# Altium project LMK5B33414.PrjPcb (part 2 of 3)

## Sheet LMK5B33414_Logic.SchDoc
size C; Date: Not shown in title block; ApprovedBy: Not shown in title block; CheckedBy: Not shown in title block; Author: Not shown in title block; CompanyName: Not shown in title block; Engineer: Not shown in title block; Organization: Not shown in title block; Address1: Not shown in title block; Address2: Not shown in title block; Address3: Not shown in title block; Address4: Not shown in title block; DocumentNumber: 2; Revision: Use project parameter SCH_Rev; SheetNumber: 2; SheetTotal: 3; PageSetup: Record=PageOptions¦CenterHorizontal=True¦CenterVertical=True¦PrintScale=1.00¦XCorrection=1.00¦YCorrection=1.00¦PrintKind=0¦BorderSize=5000000¦LeftOffset=0¦BottomOffset=0¦Orientation=2¦PaperLength=1000¦PaperWidth=1000¦Scale=100¦PaperSource=15¦PrintQuality=600¦MediaType=1¦DitherType=10¦PaperKind=Letter¦PrintScaleMode=1
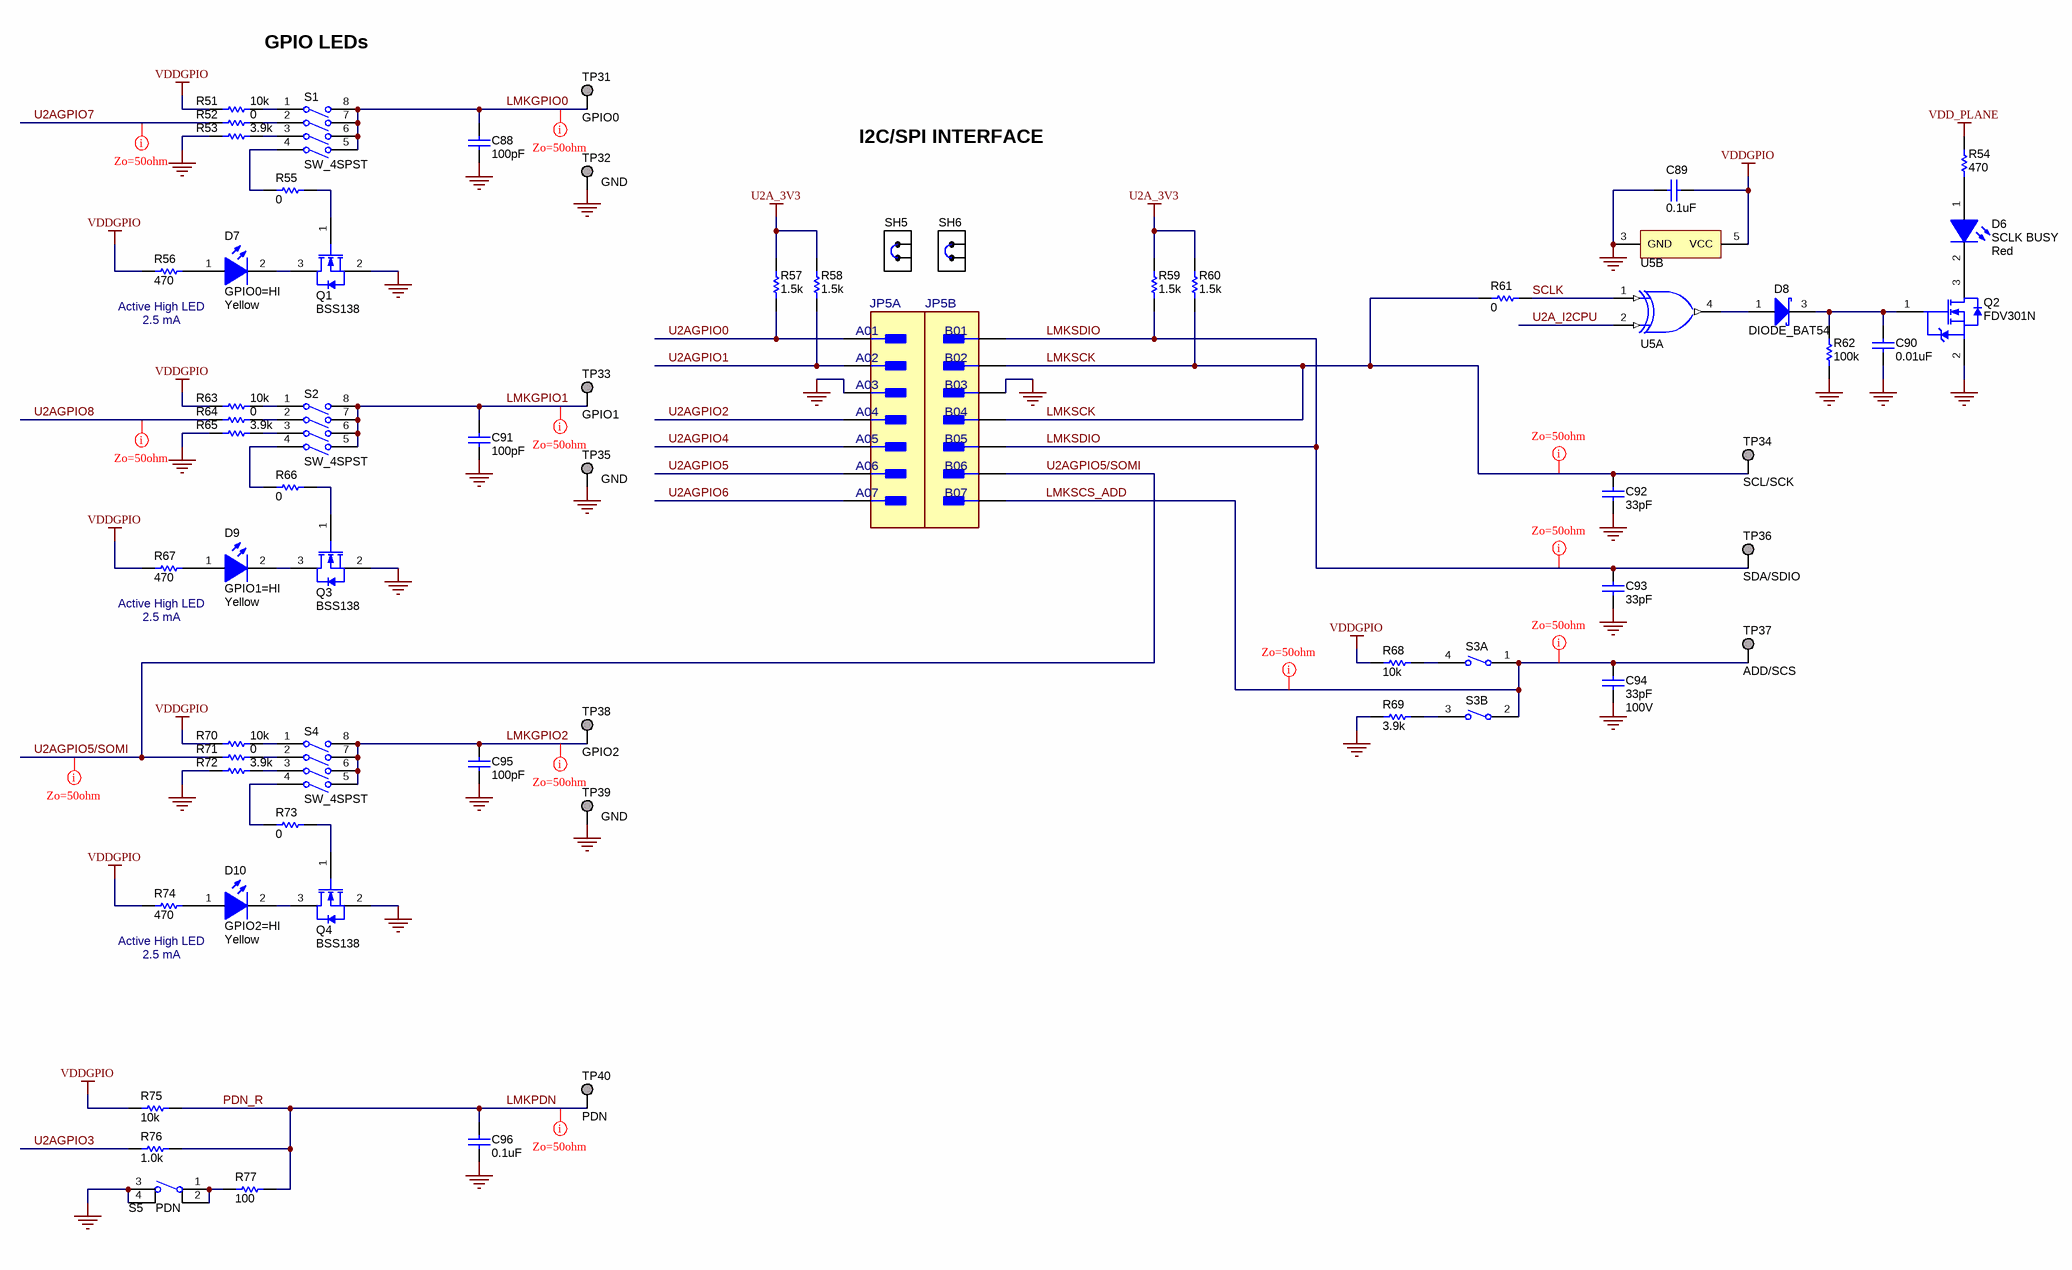
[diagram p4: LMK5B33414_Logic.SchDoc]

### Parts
C88  ValueDisplayed: 100pF  [0603]  (hidden comment: Capacitor)
C89  ValueDisplayed: 0.1uF  [0603]  (hidden comment: Capacitor)
C90  ValueDisplayed: 0.01uF  [0603]  (hidden comment: Capacitor)
C91  ValueDisplayed: 100pF  [0603]  (hidden comment: Capacitor)
C92  ValueDisplayed: 33pF  [0603]  (hidden comment: Capacitor)
C93  ValueDisplayed: 33pF  [0603]  (hidden comment: Capacitor)
C94  ValueDisplayed: 33pF  VDC_V: 100V  [0603]  (hidden comment: 06031A330JAT2A)
C95  ValueDisplayed: 100pF  [0603]  (hidden comment: Capacitor)
C96  ValueDisplayed: 0.1uF  [0603]  (hidden comment: C0603C104J3RACTU)
D6  SCLK BUSY  value Red  [LED_LTST-C170_Red]
D7  GPIO0=HI  value Yellow  [LED_LTST-C170]
D8  DIODE_BAT54  [SOT-23]
D9  GPIO1=HI  value Yellow  [LED_LTST-C170]
D10  GPIO2=HI  value Yellow  [LED_LTST-C170]
JP5  54202-G0807LF  [FP-54202-G0807LF_HDR14-MFG]  (value not drawn)  (parts A,B of 2)
Q1  BSS138  [SOT-23]
Q2  FDV301N  [SOT-23]
Q3  BSS138  [SOT-23]
Q4  BSS138  [SOT-23]
R51  ValueDisplayed: 10k  [0603]  (hidden comment: Resistor)
R52  ValueDisplayed: 0  [0603]  (hidden comment: Resistor)
R53  ValueDisplayed: 3.9k  [0603]  (hidden comment: CRCW06033K90JNEA)
R54  ValueDisplayed: 470  [0603]  (hidden comment: Resistor)
R55  ValueDisplayed: 0  [0603L]  (hidden comment: Resistor)
R56  ValueDisplayed: 470  [0603]  (hidden comment: Resistor)
R57  ValueDisplayed: 1.5k  [0603]  (hidden comment: Resistor)
R58  ValueDisplayed: 1.5k  [0603]  (hidden comment: Resistor)
R59  ValueDisplayed: 1.5k  [0603]  (hidden comment: Resistor)
R60  ValueDisplayed: 1.5k  [0603]  (hidden comment: Resistor)
R61  ValueDisplayed: 0  [0603]  (hidden comment: Resistor)
R62  ValueDisplayed: 100k  [0603]  (hidden comment: Resistor)
R63  ValueDisplayed: 10k  [0603]  (hidden comment: Resistor)
R64  ValueDisplayed: 0  [0603]  (hidden comment: Resistor)
R65  ValueDisplayed: 3.9k  [0603]  (hidden comment: CRCW06033K90JNEA)
R66  ValueDisplayed: 0  [0603L]  (hidden comment: Resistor)
R67  ValueDisplayed: 470  [0603]  (hidden comment: Resistor)
R68  ValueDisplayed: 10k  [0603]  (hidden comment: Resistor)
R69  ValueDisplayed: 3.9k  [0603]  (hidden comment: Resistor)
R70  ValueDisplayed: 10k  [0603]  (hidden comment: Resistor)
R71  ValueDisplayed: 0  [0603]  (hidden comment: Resistor)
R72  ValueDisplayed: 3.9k  [0603]  (hidden comment: CRCW06033K90JNEA)
R73  ValueDisplayed: 0  [0603L]  (hidden comment: Resistor)
R74  ValueDisplayed: 470  [0603]  (hidden comment: Resistor)
R75  ValueDisplayed: 10k  [0603]  (hidden comment: Resistor)
R76  ValueDisplayed: 1.0k  [0603]  (hidden comment: Resistor)
R77  ValueDisplayed: 100  [0603]  (hidden comment: ESR03EZPJ101)
S1  SW_4SPST  [SW_219-4LPST]
S2  SW_4SPST  [SW_219-4LPST]
S3  SW_219-2LPST  [SW_219-2LPST]  (value not drawn)  (parts A,B of 2)
S4  SW_4SPST  [SW_219-4LPST]
S5  PDN  [SW_FSM4JSMA]
SH5  SNT-100-BK-G  [SNT-100-BK-G]  (value not drawn)
SH6  SNT-100-BK-G  [SNT-100-BK-G]  (value not drawn)
TP31  GPIO0  [Keystone_5019]
TP32  GND  [Keystone_5019]
TP33  GPIO1  [Keystone_5019]
TP34  SCL/SCK  [Keystone_5019]
TP35  GND  [Keystone_5019]
TP36  SDA/SDIO  [Keystone_5019]
TP37  ADD/SCS  [Keystone_5019]
TP38  GPIO2  [Keystone_5019]
TP39  GND  [Keystone_5019]
TP40  PDN  [Keystone_5019]
U5  TI-XOR-1-2IN-5  [DBV0005A_N]  (value not drawn)  (parts A,B of 2)

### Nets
GND: C88.2 C89.1 C90.2 C91.2 C92.2 C93.2 C94.2 C95.2 C96.2 JP5.A03 JP5.B03 Q1.2(S) Q2.2(S) Q3.2(S) Q4.2(S) R53.1 R62.1 R65.1 R69.1 R72.1 S5.3 S5.4 TP32.1 TP35.1 TP39.1 U5.3(GND)
U2A_3V3: R57.2 R58.2 R59.2 R60.2
VDD_PLANE: R54.2
VDDGPIO: C89.2 R51.1 R56.2 R63.1 R67.2 R68.1 R70.1 R74.2 R75.1 U5.5(VCC)
LMKGPIO0: C88.1 S1.5(B4) S1.6(B3) S1.7(B2) S1.8(B1) TP31.1
LMKGPIO1: C91.1 S2.5(B4) S2.6(B3) S2.7(B2) S2.8(B1) TP33.1
LMKGPIO2: C95.1 S4.5(B4) S4.6(B3) S4.7(B2) S4.8(B1) TP38.1
LMKPDN: C96.1 R75.2 R76.2 R77.1 TP40.1  [also labelled PDN_R]
LMKSCK: C92.1 JP5.B02 JP5.B04 R60.1 R61.1 TP34.1
LMKSCS_ADD: C94.1 JP5.B07 S3.1(1A) S3.2(2A) TP37.1
LMKSDIO: C93.1 JP5.B01 JP5.B05 R59.1 TP36.1
SCLK: R61.2 U5.1(A)
U2A_I2CPU: U5.2(B)
U2AGPIO0: JP5.A01 R57.1
U2AGPIO1: JP5.A02 R58.1
U2AGPIO2: JP5.A04
U2AGPIO3: R76.1
U2AGPIO4: JP5.A05
U2AGPIO5: JP5.A06
U2AGPIO5/SOMI: JP5.B06 R71.2
U2AGPIO6: JP5.A07
U2AGPIO7: R52.1
U2AGPIO8: R64.1
NetC90_1: C90.1 D8.3(K) Q2.1(G) R62.2
NetD6_1: D6.1(A) R54.1
NetD6_2: D6.2(K) Q2.3(D)
NetD7_1: D7.1(A) R56.1
NetD7_2: D7.2(K) Q1.3(D)
NetD8_1: D8.1(A) U5.4(Y)
NetD9_1: D9.1(A) R67.1
NetD9_2: D9.2(K) Q3.3(D)
NetD10_1: D10.1(A) R74.1
NetD10_2: D10.2(K) Q4.3(D)
NetQ1_1: Q1.1(G) R55.2
NetQ3_1: Q3.1(G) R66.2
NetQ4_1: Q4.1(G) R73.2
NetR51_2: R51.2 S1.1(A1)
NetR52_2: R52.2 S1.2(A2)
NetR53_2: R53.2 S1.3(A3)
NetR55_1: R55.1 S1.4(A4)
NetR63_2: R63.2 S2.1(A1)
NetR64_2: R64.2 S2.2(A2)
NetR65_2: R65.2 S2.3(A3)
NetR66_1: R66.1 S2.4(A4)
NetR68_2: R68.2 S3.4(1B)
NetR69_2: R69.2 S3.3(2B)
NetR70_2: R70.2 S4.1(A1)
NetR71_1: R71.1 S4.2(A2)
NetR72_2: R72.2 S4.3(A3)
NetR73_1: R73.1 S4.4(A4)
NetR77_2: R77.2 S5.1 S5.2

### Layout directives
rule Impedance Constraint [Min = 45.00    Max = 55.00    ]: LMKGPIO0, LMKGPIO1, LMKGPIO2, LMKPDN, LMKSCK, LMKSCS_ADD, LMKSDIO, U2AGPIO5/SOMI, U2AGPIO7, U2AGPIO8

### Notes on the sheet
- GPIO LEDs
- I2C/SPI INTERFACE
- Active High LED
  2.5 mA

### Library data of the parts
C88 C91 C95 = CMP-0006763-4: CAP, CERM, 100 pF, 50 V, +/- 5%, C0G/NP0, 0603; PartNumber: 06035A101JAT2A; Manufacturer: AVX; Polarized: N; Value: 100pF; U/M: EA; ESR_ohm: 1.19d; Value1: 0.119 ohm; VDC_V: 50V; TaMin_C: -55°C; TaMax_C: 125°C; AEC Category: Q200; SizeArea_mm2: 1.28; SizeAreaWB_mm2: 4.68; SizeX_mm: 1.6; SizeY_mm: 0.8; SizeZ_mm: 1
C89 = CMP-0006857-4: CAP, CERM, 0.1 uF, 16 V, +/- 5%, X7R, 0603; PartNumber: C0603C104J4RACTU; Manufacturer: Kemet; Polarized: N; Value: 0.1uF; U/M: EA; Cap_F: 100nF; Value1: Unknown; VDC_V: 16V; TaMin_C: -55°C; TaMax_C: 125°C; AEC Category: Q200; SizeArea_mm2: 1.28; SizeAreaWB_mm2: 4.68; SizeX_mm: 1.6; SizeY_mm: 0.8; SizeZ_mm: 1
C90 = CMP-0006850-4: CAP, CERM, 0.01 uF, 50 V, +/- 5%, X7R, 0603; PartNumber: C0603C103J5RACTU; Manufacturer: Kemet; Polarized: N; Value: 0.01uF; U/M: EA; Cap_F: 10nF; Value1: Unknown; VDC_V: 50V; TaMin_C: -55°C; TaMax_C: 125°C; SizeArea_mm2: 1.28; SizeAreaWB_mm2: 4.68; SizeX_mm: 1.6; SizeY_mm: 0.8; SizeZ_mm: 1; AEC Category: Q200
C92 C93 = CMP-0006722-4: CAP, CERM, 33 pF, 100 V, +/- 5%, C0G/NP0, 0603; PartNumber: 06031A330JAT2A; Manufacturer: AVX; Polarized: N; Value: 33pF; U/M: EA; ESR_ohm: 2.09d; Value1: 0.209 ohm; VDC_V: 100V; TaMin_C: -55°C; TaMax_C: 125°C; AEC Category: Q200; SizeArea_mm2: 1.28; SizeAreaWB_mm2: 4.68; SizeX_mm: 1.6; SizeY_mm: 0.8; SizeZ_mm: 1
C94 = CMP-0006722-4: CAP, CERM, 33 pF, 100 V, +/- 5%, C0G/NP0, 0603; Manufacturer: AVX; Polarized: N; Value: 33pF; U/M: EA; ESR_ohm: 2.09d; Value1: 0.209 ohm; TaMin_C: -55°C; TaMax_C: 125°C; AEC Category: Q200; SizeArea_mm2: 1.28; SizeAreaWB_mm2: 4.68; SizeX_mm: 1.6; SizeY_mm: 0.8; SizeZ_mm: 1
C96 = CMP-0006856-6: CAP, CERM, 0.1 uF, 25 V, +/- 5%, X7R, 0603; Manufacturer: Kemet; Polarized: N; Value: 0.1uF; U/M: EA; Cap_F: 100nF; Value1: Unknown; VDC_V: 25V; TaMin_C: -55°C; TaMax_C: 125°C; AEC Category: Q200; SizeArea_mm2: 1.28; SizeAreaWB_mm2: 4.68; SizeX_mm: 1.6; SizeY_mm: 0.8; SizeZ_mm: 1
D6 = CMP-0002829-2: LED, Red, SMD; Manufacturer: Lite-On; PartNumber: LTST-C170KRKT; Type: AlInGaP; Vf_V: 2V; Io_A: 20mA; Value1: W; U/M: EA; SizeAreaWB_mm2: 6.75; SizeArea_mm2: 2.5; SizeX_mm: 2; SizeY_mm: 1.25; SizeZ_mm: 1.2
D7 D9 D10 = CMP-0002862-2: LED, Yellow , SMD; Manufacturer: Lite-On; PartNumber: LTST-C170KSKT; Type: AlInGaP; Vf_V: 2V; Io_A: 20mA; Value1: W; SizeArea_mm2: 2.5; SizeAreaWB_mm2: 6.75; SizeX_mm: 2; SizeY_mm: 1.25; SizeZ_mm: 1.2
D8 = CMP-0028451-2: Diode, Schottky, 30 V, 0.2 A, SOT-23; PartNumber: BAT54-7-F; Manufacturer: Diodes Inc.; Vf_V: 6.5dV; Value: 30V; Value1: 0.2A; Value2: 0.65V; Io_A: 2dA; TJmax_C: 125°C; SizeAreaWB_mm2: 14; SizeArea_mm2: 7.5; SizeX_mm: 2.5; SizeY_mm: 3; SizeZ_mm: 1.1; AEC Category: Q101; Green_Lifecycle: Active; Green_REACh: Passed
JP5 = CMP-0088459-1: Connector Header Surface Mount 14 position 0.100" (2.54mm); Manufacturer: Amphenol ICC; Standoff Height: 1.01mm; Voltage_V: 1.5kV; Conn Gender: Male; ContactFinish: Gold,Nickel; AEC Qualified: No; SizeZ_mm: 9.98mm; Conn Orientation: Straight; Current_A: 3A; Row_Count: 2
Q1 Q3 Q4 = CMP-0000755-1: MOSFET, N-CH, 50 V, 0.22 A, SOT-23; Manufacturer: Fairchild Semiconductor; Alternate Manufacturer: None; U/M: EA; ChType: N; Value: 50V; Rdson45_ohm: 6; Value2: 1.7 nC; QgTyp_nC: 1.7; Vgs_V: 20V; IdsMax_A: 2.2dA; AEC Category: Q101; SizeArea_mm2: 7.5; SizeAreaWB_mm2: 14; SizeX_mm: 2.5; SizeY_mm: 3; SizeZ_mm: 1.1
Q2 = CMP-0000281-1: MOSFET, N-CH, 25 V, 0.22 A, SOT-23; Manufacturer: Fairchild Semiconductor; Alternate Manufacturer: None; U/M: EA; ChType: N; Value: 25V; Rdson45_ohm: 4; Value2: 0.49 nC; QgTyp_nC: 0.49; Vgs_V: 8V; IdsMax_A: 2.2dA; SizeAreaWB_mm2: 14; SizeArea_mm2: 7.5; SizeX_mm: 2.5; SizeY_mm: 3; SizeZ_mm: 1.1; AEC Category: Q101
R51 R63 R68 R70 R75 = CMP-0025701-4: RES, 10 k, 5%, 0.1 W, AEC-Q200 Grade 0, 0603; PartNumber: CRCW060310K0JNEA; Manufacturer: Vishay-Dale; Value: 10k; Value_Code: 10k0; Power_W: 100mW; Value2: 0.1W; VDC_V: 75V; TempCo: 200 ppm/C; EIA_Code: E24; SizeArea_mm2: 1.28; SizeX_mm: 1.6; SizeY_mm: 0.8; SizeZ_mm: 1; AEC Category: Q200; AEC Qualified: Y; AEC Grade: 0
R52 R61 R64 R71 = CMP-0025697-4: RES, 0, 5%, 0.1 W, AEC-Q200 Grade 0, 0603; PartNumber: CRCW06030000Z0EA; Manufacturer: Vishay-Dale; Value: 0; Value_Code: 0000; Power_W: 100mW; Value2: 0.1W; VDC_V: 75V; TempCo: 200 ppm/C; EIA_Code: E24; AEC Category: Q200; AEC Qualified: Y; SizeArea_mm2: 1.28; SizeX_mm: 1.6; SizeY_mm: 0.8; SizeZ_mm: 1
R53 R65 R72 = CMP-0025799-4: RES, 3.9 k, 5%, 0.1 W, AEC-Q200 Grade 0, 0603; Manufacturer: Vishay-Dale; Value: 3.9k; Value_Code: 3k90; Power_W: 100mW; Value2: 0.1W; VDC_V: 75V; TempCo: 200 ppm/C; EIA_Code: E24; SizeArea_mm2: 1.28; SizeX_mm: 1.6; SizeY_mm: 0.8; SizeZ_mm: 1; AEC Category: Q200; AEC Qualified: Y; AEC Grade: 0
R54 R56 R67 R74 = CMP-0025813-4: RES, 470, 5%, 0.1 W, AEC-Q200 Grade 0, 0603; PartNumber: CRCW0603470RJNEA; Manufacturer: Vishay-Dale; Value: 470; Value_Code: 470R; Power_W: 100mW; Value2: 0.1W; VDC_V: 75V; TempCo: 200 ppm/C; EIA_Code: E24; SizeArea_mm2: 1.28; SizeX_mm: 1.6; SizeY_mm: 0.8; SizeZ_mm: 1; AEC Category: Q200; AEC Qualified: Y; AEC Grade: 0
R55 R66 R73 = CMP-0025697-4: RES, 0, 5%, 0.1 W, AEC-Q200 Grade 0, 0603; PartNumber: CRCW06030000Z0EA; Manufacturer: Vishay-Dale; Value: 0; Value_Code: 0000; Power_W: 100mW; Value2: 0.1W; VDC_V: 75V; TempCo: 200 ppm/C; EIA_Code: E24; SizeArea_mm2: 1.28; SizeX_mm: 1.6; SizeY_mm: 0.8; SizeZ_mm: 1; AEC Category: Q200; AEC Qualified: Y
R57-R60 = CMP-0025733-4: RES, 1.5 k, 5%, 0.1 W, AEC-Q200 Grade 0, 0603; PartNumber: CRCW06031K50JNEA; Manufacturer: Vishay-Dale; Value: 1.5k; Value_Code: 1k50; Power_W: 100mW; Value2: 0.1W; VDC_V: 75V; TempCo: 200 ppm/C; EIA_Code: E24; SizeArea_mm2: 1.28; SizeX_mm: 1.6; SizeY_mm: 0.8; SizeZ_mm: 1; AEC Category: Q200; AEC Qualified: Y; AEC Grade: 0
R62 = CMP-0025698-4: RES, 100 k, 5%, 0.1 W, AEC-Q200 Grade 0, 0603; PartNumber: CRCW0603100KJNEA; Manufacturer: Vishay-Dale; Value: 100k; Power_W: 100mW; Value2: 0.1W; VDC_V: 75V; TempCo: 200 ppm/C; EIA_Code: E24; SizeArea_mm2: 1.28; SizeX_mm: 1.6; SizeY_mm: 0.8; SizeZ_mm: 1; AEC Category: Q200; AEC Qualified: Y; AEC Grade: 0
R69 = CMP-0025799-4: RES, 3.9 k, 5%, 0.1 W, AEC-Q200 Grade 0, 0603; PartNumber: CRCW06033K90JNEA; Manufacturer: Vishay-Dale; Value: 3.9k; Value_Code: 3k90; Power_W: 100mW; Value2: 0.1W; VDC_V: 75V; TempCo: 200 ppm/C; EIA_Code: E24; SizeArea_mm2: 1.28; SizeX_mm: 1.6; SizeY_mm: 0.8; SizeZ_mm: 1; AEC Category: Q200; AEC Qualified: Y; AEC Grade: 0
R76 = CMP-0025729-4: RES, 1.0 k, 5%, 0.1 W, AEC-Q200 Grade 0, 0603; PartNumber: CRCW06031K00JNEA; Manufacturer: Vishay-Dale; Value: 1.0k; Res_ohm: 1k; Value_Code: 1k00; Power_W: 100mW; Value2: 0.1W; VDC_V: 75V; TempCo: 200 ppm/C; EIA_Code: E24; SizeArea_mm2: 1.28; SizeX_mm: 1.6; SizeY_mm: 0.8; SizeZ_mm: 1; AEC Category: Q200; AEC Qualified: Y; AEC Grade: 0
R77 = CMP-0025882-3: RES, 100, 5%, 0.25 W, AEC-Q200 Grade 0, 0603; Manufacturer: Rohm; Value: 100; Value_Code: 100R; Power_W: 250mW; Value2: 0.25W; VDC_V: 150V; TempCo: 200 ppm/C; EIA_Code: E24; SizeArea_mm2: 1.28; SizeX_mm: 1.6; SizeY_mm: 0.8; SizeZ_mm: 1; AEC Category: Q200; AEC Qualified: Y; AEC Grade: 0; U/M: EA
S1 S2 S4 = CMP-0002176-2: Switch, SPST 4 Pos, Top Actuated, SMT; PartNumber: 219-4LPST; Manufacturer: CTS Electrocomponents; VDC_V: 50V; SwitchFunction: Off-On; PositionCount: 4; CurrentRating_mA: 100A
S3 = CMP-0002127-2: Switch, Slide, SPST 2 poles, SMT; Manufacturer: CTS Electrocomponents; VDC_V: 20V; SwitchFunction: Off-On; PositionCount: 2; CurrentRating_mA: 100A
S5 = CMP-0002134-3: Switch, Tactile, SPST-NO, 0.05A, 12V, SMT; PartNumber: FSM4JSMA; Manufacturer: TE Connectivity; CurrentRating_mA: 50A; PositionCount: 1; SwitchFunction: Off-Mom
SH5 SH6 = CMP-0003623-3: Shunt, 100mil, Gold plated, Black; Manufacturer: Samtec; Alternate Manufacturer: 3M; Alternate PartNumber: 969102-0000-DA; Value: 1x2; Note: You can "mate" this to a header by matching the designator.  i.e. use SH-J3 for header J3
TP31-TP40 = CMP-0055162-1: Test Point, Miniature, SMT; Manufacturer: Keystone; PartNumber: 5019; CNHeader: FALSE; Green_Lifecycle: Active; Green_REACh: Passed; CT: TRUE
U5 = CMP-0052046-2: Single 2-Input Exclusive-OR Gate, DBV0005A (SOT-23-5); PartNumber: SN74LVC1G86DBVR; Manufacturer: Texas Instruments; Generic Part Number: SN74LVC1G86; SizeArea_mm2: 8.12; SizeAreaWB_mm2: 14.82; SizeX_mm: 2.8; SizeY_mm: 2.9; SizeZ_mm: 1.45; CompType: IC; 3-State Output: No; AEC Category: Q200; AEC Qualified: N; Bits(#): 1; F @ Nom Voltage(Max)(Mhz): 150; Gate Type: XOR; ICC @ Nom Voltage(Max)(mA): 0.01; Input Type: CMOS/TTL; Logic: True; Output Drive (IOL/IOH)(Max)(mA): 32/-32; Output Type: CMOS; Rating: Catalog; tpd @ Nom Voltage(Max)(ns): 9.9,5.5,5,4; VCC(Max)(V): 5.5; VCC(Min)(V): 1.65; Voltage(Nom)(V): 1.8,2.5,3.3,5

## Sheet LMK5B33414_Outputs_A.SchDoc
size C; Date: Not shown in title block; ApprovedBy: Not shown in title block; CheckedBy: Not shown in title block; Author: Not shown in title block; CompanyName: Not shown in title block; Engineer: Not shown in title block; Organization: Not shown in title block; Address1: Not shown in title block; Address2: Not shown in title block; Address3: Not shown in title block; Address4: Not shown in title block; DocumentNumber: 2; Revision: Use project parameter SCH_Rev; SheetNumber: 2; SheetTotal: 3; PageSetup: Record=PageOptions¦CenterHorizontal=True¦CenterVertical=True¦PrintScale=1.00¦XCorrection=1.00¦YCorrection=1.00¦PrintKind=0¦BorderSize=5000000¦LeftOffset=0¦BottomOffset=0¦Orientation=2¦PaperLength=1000¦PaperWidth=1000¦Scale=100¦PaperSource=15¦PrintQuality=600¦MediaType=1¦DitherType=10¦PaperKind=Letter¦PrintScaleMode=1
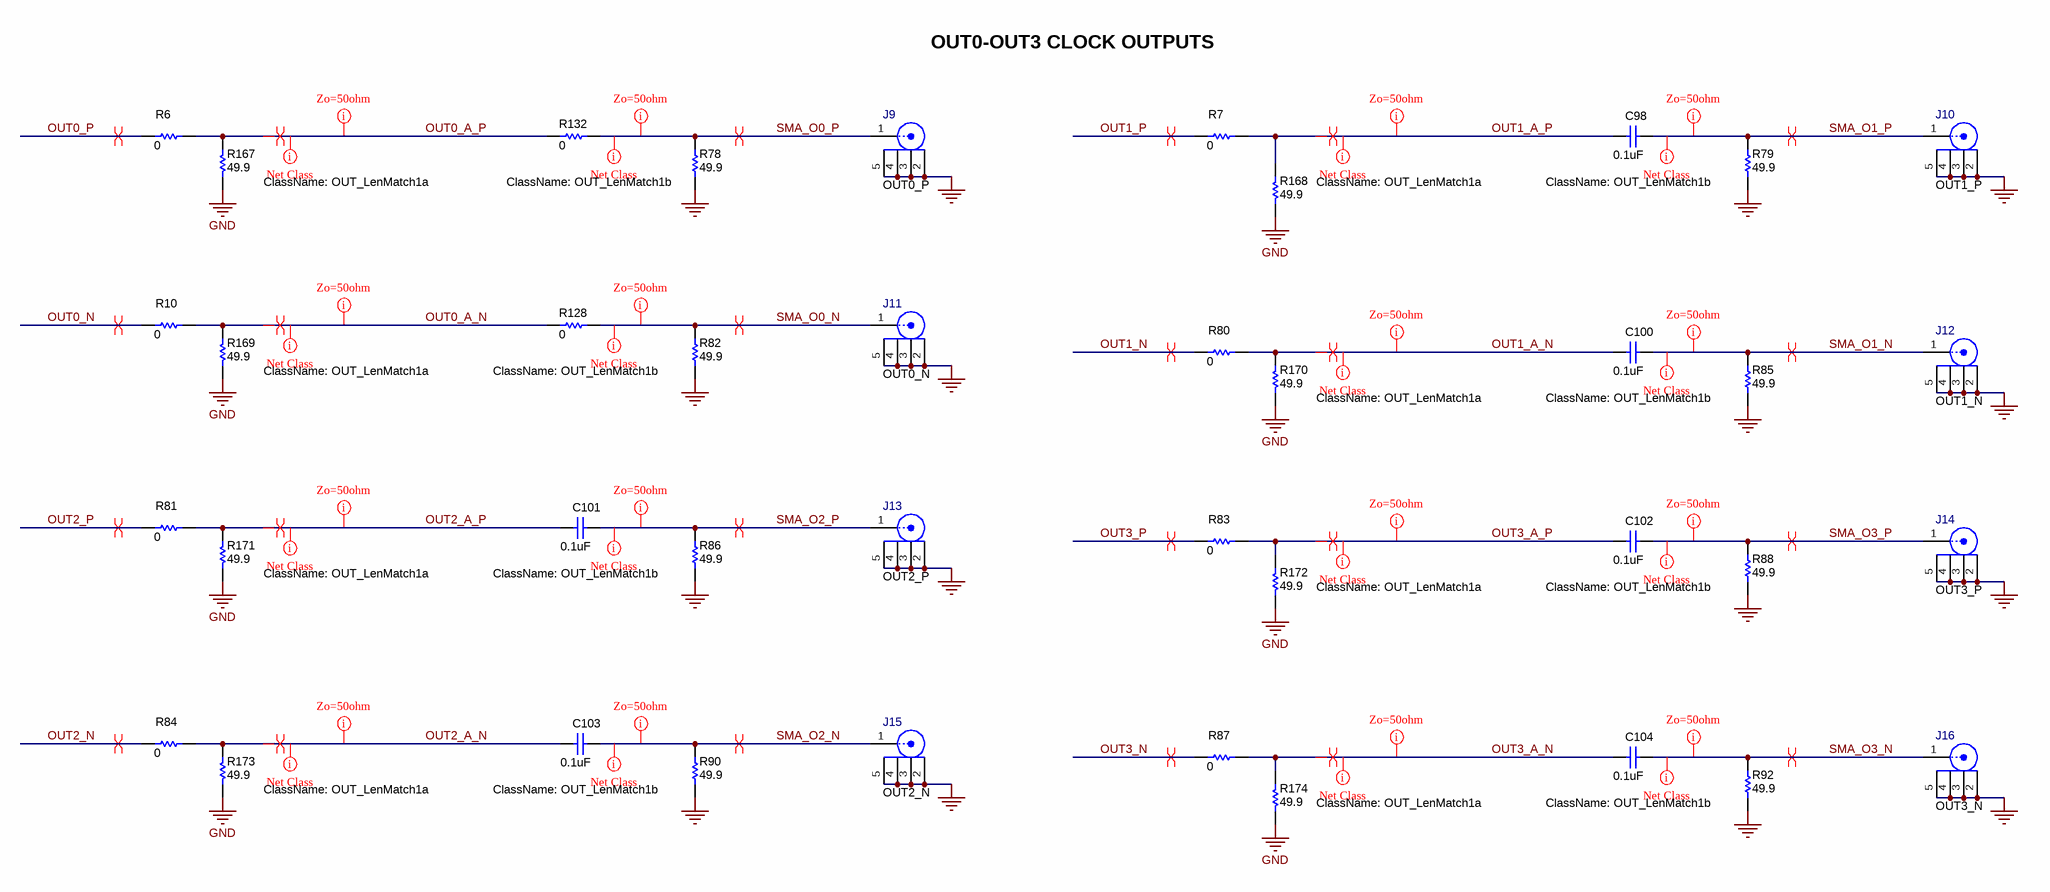
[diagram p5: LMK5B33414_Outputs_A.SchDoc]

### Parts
C98  ValueDisplayed: 0.1uF  [0402L]  (hidden comment: GRM155R71E104KE14D)
C100  ValueDisplayed: 0.1uF  [0402L]  (hidden comment: GRM155R71E104KE14D)
C101  ValueDisplayed: 0.1uF  [0402L]  (hidden comment: GRM155R71E104KE14D)
C102  ValueDisplayed: 0.1uF  [0402L]  (hidden comment: GRM155R71E104KE14D)
C103  ValueDisplayed: 0.1uF  [0402L]  (hidden comment: GRM155R71E104KE14D)
C104  ValueDisplayed: 0.1uF  [0402L]  (hidden comment: GRM155R71E104KE14D)
J9  OUT0_P  [FP-CON-SMA-EDGE-S_CONN_JACK-MFG]
J10  OUT1_P  [FP-CON-SMA-EDGE-S_CONN_JACK-MFG]
J11  OUT0_N  [FP-CON-SMA-EDGE-S_CONN_JACK-MFG]
J12  OUT1_N  [FP-CON-SMA-EDGE-S_CONN_JACK-MFG]
J13  OUT2_P  [FP-CON-SMA-EDGE-S_CONN_JACK-MFG]
J14  OUT3_P  [FP-CON-SMA-EDGE-S_CONN_JACK-MFG]
J15  OUT2_N  [FP-CON-SMA-EDGE-S_CONN_JACK-MFG]
J16  OUT3_N  [FP-CON-SMA-EDGE-S_CONN_JACK-MFG]
R6  ValueDisplayed: 0  [0402L]  (hidden comment: RK73Z1ETTP)
R7  ValueDisplayed: 0  [0402L]  (hidden comment: RK73Z1ETTP)
R10  ValueDisplayed: 0  [0402L]  (hidden comment: RK73Z1ETTP)
R78  ValueDisplayed: 49.9  [0402S]  (hidden comment: ERJ-2RKF49R9X)
R79  ValueDisplayed: 49.9  [0402S]  (hidden comment: ERJ-2RKF49R9X)
R80  ValueDisplayed: 0  [0402L]  (hidden comment: RK73Z1ETTP)
R81  ValueDisplayed: 0  [0402L]  (hidden comment: RK73Z1ETTP)
R82  ValueDisplayed: 49.9  [0402S]  (hidden comment: ERJ-2RKF49R9X)
R83  ValueDisplayed: 0  [0402L]  (hidden comment: RK73Z1ETTP)
R84  ValueDisplayed: 0  [0402L]  (hidden comment: RK73Z1ETTP)
R85  ValueDisplayed: 49.9  [0402S]  (hidden comment: ERJ-2RKF49R9X)
R86  ValueDisplayed: 49.9  [0402S]  (hidden comment: ERJ-2RKF49R9X)
R87  ValueDisplayed: 0  [0402L]  (hidden comment: RK73Z1ETTP)
R88  ValueDisplayed: 49.9  [0402S]  (hidden comment: ERJ-2RKF49R9X)
R90  ValueDisplayed: 49.9  [0402S]  (hidden comment: ERJ-2RKF49R9X)
R92  ValueDisplayed: 49.9  [0402S]  (hidden comment: ERJ-2RKF49R9X)
R128  ValueDisplayed: 0  [0402L]  (hidden comment: RK73Z1ETTP)
R132  ValueDisplayed: 0  [0402L]  (hidden comment: RK73Z1ETTP)
R167  ValueDisplayed: 49.9  [0402S]  (hidden comment: ERJ-2RKF49R9X)
R168  ValueDisplayed: 49.9  [0402S]  (hidden comment: ERJ-2RKF49R9X)
R169  ValueDisplayed: 49.9  [0402S]  (hidden comment: ERJ-2RKF49R9X)
R170  ValueDisplayed: 49.9  [0402S]  (hidden comment: ERJ-2RKF49R9X)
R171  ValueDisplayed: 49.9  [0402S]  (hidden comment: ERJ-2RKF49R9X)
R172  ValueDisplayed: 49.9  [0402S]  (hidden comment: ERJ-2RKF49R9X)
R173  ValueDisplayed: 49.9  [0402S]  (hidden comment: ERJ-2RKF49R9X)
R174  ValueDisplayed: 49.9  [0402S]  (hidden comment: ERJ-2RKF49R9X)

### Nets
GND: J9.2 J9.3 J9.4 J9.5 J10.2 J10.3 J10.4 J10.5 J11.2 J11.3 J11.4 J11.5 J12.2 J12.3 J12.4 J12.5 J13.2 J13.3 J13.4 J13.5 J14.2 J14.3 J14.4 J14.5 J15.2 J15.3 J15.4 J15.5 J16.2 J16.3 J16.4 J16.5 R78.1 R79.1 R82.1 R85.1 R86.1 R88.1 R90.1 R92.1 R167.2 R168.2 R169.2 R170.2 R171.2 R172.2 R173.2 R174.2
OUT0_A_N: R10.2 R128.1 R169.1
OUT0_A_P: R6.2 R132.1 R167.1
OUT0_N: R10.1
OUT0_P: R6.1
OUT1_A_N: C100.2 R80.2 R170.1
OUT1_A_P: C98.2 R7.2 R168.1
OUT1_N: R80.1
OUT1_P: R7.1
OUT2_A_N: C103.2 R84.2 R173.1
OUT2_A_P: C101.2 R81.2 R171.1
OUT2_N: R84.1
OUT2_P: R81.1
OUT3_A_N: C104.2 R87.2 R174.1
OUT3_A_P: C102.2 R83.2 R172.1
OUT3_N: R87.1
OUT3_P: R83.1
SMA_O0_N: J11.1 R82.2 R128.2
SMA_O0_P: J9.1 R78.2 R132.2
SMA_O1_N: C100.1 J12.1 R85.2
SMA_O1_P: C98.1 J10.1 R79.2
SMA_O2_N: C103.1 J15.1 R90.2
SMA_O2_P: C101.1 J13.1 R86.2
SMA_O3_N: C104.1 J16.1 R92.2
SMA_O3_P: C102.1 J14.1 R88.2

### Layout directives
rule Impedance Constraint [Min = 45.00    Max = 55.00    ]: OUT0_A_N, OUT0_A_P, OUT1_A_N, OUT1_A_P, OUT2_A_N, OUT2_A_P, OUT3_A_N, OUT3_A_P, SMA_O0_N, SMA_O0_P, SMA_O1_N, SMA_O1_P, SMA_O2_N, SMA_O2_P, SMA_O3_N, SMA_O3_P
differential pair: OUT0_A_N, OUT0_A_P, OUT0_N, OUT0_P, OUT1_A_N, OUT1_A_P, OUT1_N, OUT1_P, OUT2_A_N, OUT2_A_P, OUT2_N, OUT2_P, OUT3_A_N, OUT3_A_P, OUT3_N, OUT3_P, SMA_O0_N, SMA_O0_P, SMA_O1_N, SMA_O1_P, SMA_O2_N, SMA_O2_P, SMA_O3_N, SMA_O3_P
net class OUT_LenMatch1a: OUT0_A_N, OUT0_A_P, OUT1_A_N, OUT1_A_P, OUT2_A_N, OUT2_A_P, OUT3_A_N, OUT3_A_P
net class OUT_LenMatch1b: SMA_O0_N, SMA_O0_P, SMA_O1_N, SMA_O1_P, SMA_O2_N, SMA_O2_P, SMA_O3_N, SMA_O3_P

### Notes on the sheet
- OUT0-OUT3 CLOCK OUTPUTS

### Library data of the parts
C98 C100-C104 = CMP-0006659-2: CAP, CERM, 0.1 uF, 25 V, +/- 10%, X7R, 0402; Manufacturer: MuRata; TaMin_C: -55°C; Polarized: N; SizeAreaWB_mm2: 3; Value1: Unknown; U/M: EA; Value: 0.1uF; TaMax_C: 125°C; SizeZ_mm: 0.6; SizeX_mm: 1; SizeY_mm: 0.5; Cap_Case: 0402; Value2: 25V; CompType: Capacitor; Cap_F: 100nF; AEC Category: Q200
J9-J16 = CMP-0088000-4: CONN SMA JACK STR EDGE MNT; Manufacturer: RF Solutions Ltd.; PartNumber: CON-SMA-EDGE-S; ContactFinish: Gold; Shrouded: true
R6 R7 R10 R80 R81 R83 R84 R87 = CMP-0027007-2: RES, 0, 5%, 0.063 W, AEC-Q200 Grade 0, 0402; Manufacturer: KOA Speer; Power_W: 63mW; TempCo: ppm/C; Value_Code: 0000; U/M: EA; Value: 0; EIA_Code: E24; SizeX_mm: 1; SizeY_mm: 0.5; SizeZ_mm: 0.6; Value2: 0.063W; CompType: Resistor; AEC Qualified: Y; AEC Category: Q200
R78 R79 R82 R85 R86 R88 R90 R92 = CMP-0026703-1: RES, 49.9, 1%, 0.1 W, AEC-Q200 Grade 0, 0402; Manufacturer: Panasonic; Value: 49.9; Value_Code: 49R9; Power_W: 100mW; Value2: 0.1W; VDC_V: 50V; TempCo: 100 ppm/C; EIA_Code: E96; SizeArea_mm2: 0.5; SizeX_mm: 1; SizeZ_mm: 0.6; AEC Category: Q200; AEC Qualified: Y; AEC Grade: 0; U/M: EA
R128 = CMP-0027007-2: RES, 0, 5%, 0.063 W, AEC-Q200 Grade 0, 0402; Manufacturer: KOA Speer; TempCo: ppm/C; U/M: EA; Value: 0; SizeZ_mm: 0.6; SizeX_mm: 1; SizeY_mm: 0.5; Value2: 0.063W; CompType: Resistor; AEC Qualified: Y; AEC Category: Q200; Power_W: 63mW; Value_Code: 0000; EIA_Code: E24
R132 = CMP-0027007-2: RES, 0, 5%, 0.063 W, AEC-Q200 Grade 0, 0402; Manufacturer: KOA Speer; TempCo: ppm/C; U/M: EA; Value: 0; SizeZ_mm: 0.6; SizeX_mm: 1; SizeY_mm: 0.5; Value2: 0.063W; AEC Qualified: Y; AEC Category: Q200; Power_W: 63mW; Value_Code: 0000; EIA_Code: E24
R167-R174 = CMP-0026703-1: RES, 49.9, 1%, 0.1 W, AEC-Q200 Grade 0, 0402; Manufacturer: Panasonic; Power_W: 100mW; TempCo: 100 ppm/C; Value_Code: 49R9; Value: 49.9; EIA_Code: E96; SizeX_mm: 1; SizeY_mm: 0.5; SizeZ_mm: 0.6; Value2: 0.1W; AEC Qualified: Y; VDC_V: 50V; AEC Category: Q200; AEC Grade: 0; U/M: EA

## Sheet LMK5B33414_Outputs_B.SchDoc
size C; Date: Not shown in title block; ApprovedBy: Not shown in title block; CheckedBy: Not shown in title block; Author: Not shown in title block; CompanyName: Not shown in title block; Engineer: Not shown in title block; Organization: Not shown in title block; Address1: Not shown in title block; Address2: Not shown in title block; Address3: Not shown in title block; Address4: Not shown in title block; DocumentNumber: 2; Revision: Use project parameter SCH_Rev; SheetNumber: 2; SheetTotal: 3; PageSetup: Record=PageOptions¦CenterHorizontal=True¦CenterVertical=True¦PrintScale=1.00¦XCorrection=1.00¦YCorrection=1.00¦PrintKind=0¦BorderSize=5000000¦LeftOffset=0¦BottomOffset=0¦Orientation=2¦PaperLength=1000¦PaperWidth=1000¦Scale=100¦PaperSource=15¦PrintQuality=600¦MediaType=1¦DitherType=10¦PaperKind=Letter¦PrintScaleMode=1
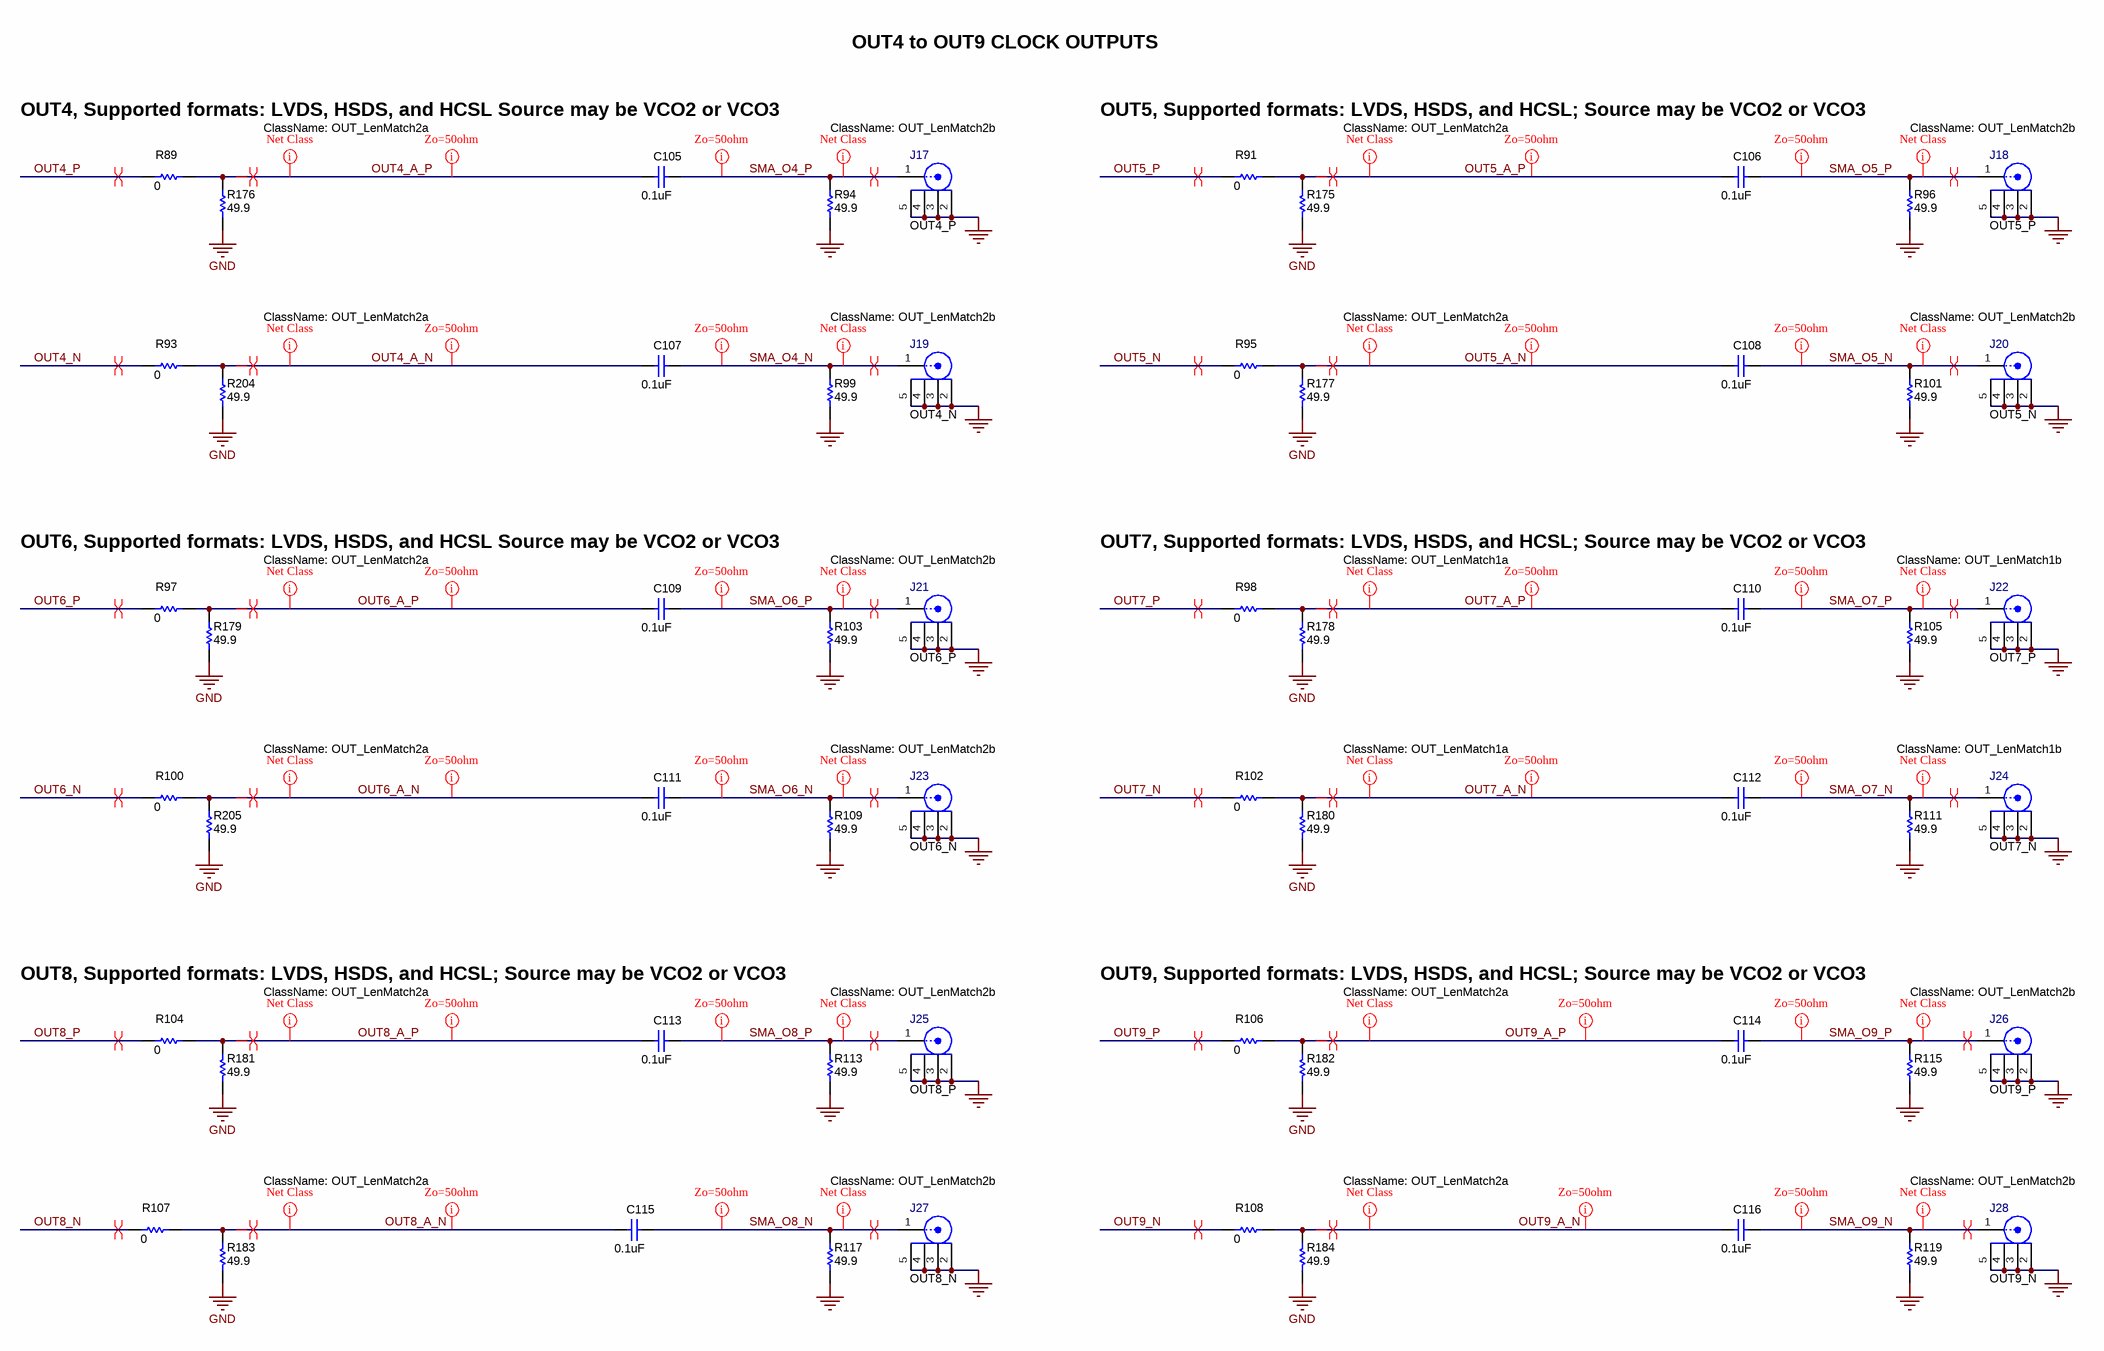
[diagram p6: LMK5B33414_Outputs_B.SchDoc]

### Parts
C105  ValueDisplayed: 0.1uF  [0402L]  (hidden comment: GRM155R71E104KE14D)
C106  ValueDisplayed: 0.1uF  [0402L]  (hidden comment: GRM155R71E104KE14D)
C107  ValueDisplayed: 0.1uF  [0402L]  (hidden comment: GRM155R71E104KE14D)
C108  ValueDisplayed: 0.1uF  [0402L]  (hidden comment: GRM155R71E104KE14D)
C109  ValueDisplayed: 0.1uF  [0402L]  (hidden comment: GRM155R71E104KE14D)
C110  ValueDisplayed: 0.1uF  [0402L]  (hidden comment: GRM155R71E104KE14D)
C111  ValueDisplayed: 0.1uF  [0402L]  (hidden comment: GRM155R71E104KE14D)
C112  ValueDisplayed: 0.1uF  [0402L]  (hidden comment: GRM155R71E104KE14D)
C113  ValueDisplayed: 0.1uF  [0402L]  (hidden comment: GRM155R71E104KE14D)
C114  ValueDisplayed: 0.1uF  [0402L]  (hidden comment: GRM155R71E104KE14D)
C115  ValueDisplayed: 0.1uF  [0402L]  (hidden comment: GRM155R71E104KE14D)
C116  ValueDisplayed: 0.1uF  [0402L]  (hidden comment: GRM155R71E104KE14D)
J17  OUT4_P  [FP-CON-SMA-EDGE-S_CONN_JACK-MFG]
J18  OUT5_P  [FP-CON-SMA-EDGE-S_CONN_JACK-MFG]
J19  OUT4_N  [FP-CON-SMA-EDGE-S_CONN_JACK-MFG]
J20  OUT5_N  [FP-CON-SMA-EDGE-S_CONN_JACK-MFG]
J21  OUT6_P  [FP-CON-SMA-EDGE-S_CONN_JACK-MFG]
J22  OUT7_P  [FP-CON-SMA-EDGE-S_CONN_JACK-MFG]
J23  OUT6_N  [FP-CON-SMA-EDGE-S_CONN_JACK-MFG]
J24  OUT7_N  [FP-CON-SMA-EDGE-S_CONN_JACK-MFG]
J25  OUT8_P  [FP-CON-SMA-EDGE-S_CONN_JACK-MFG]
J26  OUT9_P  [FP-CON-SMA-EDGE-S_CONN_JACK-MFG]
J27  OUT8_N  [FP-CON-SMA-EDGE-S_CONN_JACK-MFG]
J28  OUT9_N  [FP-CON-SMA-EDGE-S_CONN_JACK-MFG]
R89  ValueDisplayed: 0  [0402L]  (hidden comment: RK73Z1ETTP)
R91  ValueDisplayed: 0  [0402L]  (hidden comment: RK73Z1ETTP)
R93  ValueDisplayed: 0  [0402L]  (hidden comment: RK73Z1ETTP)
R94  ValueDisplayed: 49.9  [0402S]  (hidden comment: ERJ-2RKF49R9X)
R95  ValueDisplayed: 0  [0402L]  (hidden comment: RK73Z1ETTP)
R96  ValueDisplayed: 49.9  [0402S]  (hidden comment: ERJ-2RKF49R9X)
R97  ValueDisplayed: 0  [0402L]  (hidden comment: RK73Z1ETTP)
R98  ValueDisplayed: 0  [0402L]  (hidden comment: RK73Z1ETTP)
R99  ValueDisplayed: 49.9  [0402S]  (hidden comment: ERJ-2RKF49R9X)
R100  ValueDisplayed: 0  [0402L]  (hidden comment: RK73Z1ETTP)
R101  ValueDisplayed: 49.9  [0402S]  (hidden comment: ERJ-2RKF49R9X)
R102  ValueDisplayed: 0  [0402L]  (hidden comment: RK73Z1ETTP)
R103  ValueDisplayed: 49.9  [0402S]  (hidden comment: ERJ-2RKF49R9X)
R104  ValueDisplayed: 0  [0402L]  (hidden comment: RK73Z1ETTP)
R105  ValueDisplayed: 49.9  [0402S]  (hidden comment: ERJ-2RKF49R9X)
R106  ValueDisplayed: 0  [0402L]  (hidden comment: RK73Z1ETTP)
R107  ValueDisplayed: 0  [0402L]  (hidden comment: RK73Z1ETTP)
R108  ValueDisplayed: 0  [0402L]  (hidden comment: RK73Z1ETTP)
R109  ValueDisplayed: 49.9  [0402S]  (hidden comment: ERJ-2RKF49R9X)
R111  ValueDisplayed: 49.9  [0402S]  (hidden comment: ERJ-2RKF49R9X)
R113  ValueDisplayed: 49.9  [0402S]  (hidden comment: ERJ-2RKF49R9X)
R115  ValueDisplayed: 49.9  [0402S]  (hidden comment: ERJ-2RKF49R9X)
R117  ValueDisplayed: 49.9  [0402S]  (hidden comment: ERJ-2RKF49R9X)
R119  ValueDisplayed: 49.9  [0402S]  (hidden comment: ERJ-2RKF49R9X)
R175  ValueDisplayed: 49.9  [0402S]  (hidden comment: ERJ-2RKF49R9X)
R176  ValueDisplayed: 49.9  [0402S]  (hidden comment: ERJ-2RKF49R9X)
R177  ValueDisplayed: 49.9  [0402S]  (hidden comment: ERJ-2RKF49R9X)
R178  ValueDisplayed: 49.9  [0402S]  (hidden comment: ERJ-2RKF49R9X)
R179  ValueDisplayed: 49.9  [0402S]  (hidden comment: ERJ-2RKF49R9X)
R180  ValueDisplayed: 49.9  [0402S]  (hidden comment: ERJ-2RKF49R9X)
R181  ValueDisplayed: 49.9  [0402S]  (hidden comment: ERJ-2RKF49R9X)
R182  ValueDisplayed: 49.9  [0402S]  (hidden comment: ERJ-2RKF49R9X)
R183  ValueDisplayed: 49.9  [0402S]  (hidden comment: ERJ-2RKF49R9X)
R184  ValueDisplayed: 49.9  [0402S]  (hidden comment: ERJ-2RKF49R9X)
R204  ValueDisplayed: 49.9  [0402S]  (hidden comment: ERJ-2RKF49R9X)
R205  ValueDisplayed: 49.9  [0402S]  (hidden comment: ERJ-2RKF49R9X)

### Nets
GND: J17.2 J17.3 J17.4 J17.5 J18.2 J18.3 J18.4 J18.5 J19.2 J19.3 J19.4 J19.5 J20.2 J20.3 J20.4 J20.5 J21.2 J21.3 J21.4 J21.5 J22.2 J22.3 J22.4 J22.5 J23.2 J23.3 J23.4 J23.5 J24.2 J24.3 J24.4 J24.5 J25.2 J25.3 J25.4 J25.5 J26.2 J26.3 J26.4 J26.5 J27.2 J27.3 J27.4 J27.5 J28.2 J28.3 J28.4 J28.5 R94.1 R96.1 R99.1 R101.1 R103.1 R105.1 R109.1 R111.1 R113.1 R115.1 R117.1 R119.1 R175.2 R176.2 R177.2 R178.2 R179.2 R180.2 R181.2 R182.2 R183.2 R184.2 R204.2 R205.2
OUT4_A_N: C107.2 R93.2 R204.1
OUT4_A_P: C105.2 R89.2 R176.1
OUT4_N: R93.1
OUT4_P: R89.1
OUT5_A_N: C108.2 R95.2 R177.1
OUT5_A_P: C106.2 R91.2 R175.1
OUT5_N: R95.1
OUT5_P: R91.1
OUT6_A_N: C111.2 R100.2 R205.1
OUT6_A_P: C109.2 R97.2 R179.1
OUT6_N: R100.1
OUT6_P: R97.1
OUT7_A_N: C112.2 R102.2 R180.1
OUT7_A_P: C110.2 R98.2 R178.1
OUT7_N: R102.1
OUT7_P: R98.1
OUT8_A_N: C115.2 R107.2 R183.1
OUT8_A_P: C113.2 R104.2 R181.1
OUT8_N: R107.1
OUT8_P: R104.1
OUT9_A_N: C116.2 R108.2 R184.1
OUT9_A_P: C114.2 R106.2 R182.1
OUT9_N: R108.1
OUT9_P: R106.1
SMA_O4_N: C107.1 J19.1 R99.2
SMA_O4_P: C105.1 J17.1 R94.2
SMA_O5_N: C108.1 J20.1 R101.2
SMA_O5_P: C106.1 J18.1 R96.2
SMA_O6_N: C111.1 J23.1 R109.2
SMA_O6_P: C109.1 J21.1 R103.2
SMA_O7_N: C112.1 J24.1 R111.2
SMA_O7_P: C110.1 J22.1 R105.2
SMA_O8_N: C115.1 J27.1 R117.2
SMA_O8_P: C113.1 J25.1 R113.2
SMA_O9_N: C116.1 J28.1 R119.2
SMA_O9_P: C114.1 J26.1 R115.2

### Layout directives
rule Impedance Constraint [Min = 45.00    Max = 55.00    ]: OUT4_A_N, OUT4_A_P, OUT5_A_N, OUT5_A_P, OUT6_A_N, OUT6_A_P, OUT7_A_N, OUT7_A_P, OUT8_A_N, OUT8_A_P, OUT9_A_N, OUT9_A_P, SMA_O4_N, SMA_O4_P, SMA_O5_N, SMA_O5_P, SMA_O6_N, SMA_O6_P, SMA_O7_N, SMA_O7_P, SMA_O8_N, SMA_O8_P, SMA_O9_N, SMA_O9_P
differential pair: OUT4_A_N, OUT4_A_P, OUT4_N, OUT4_P, OUT5_A_N, OUT5_A_P, OUT5_N, OUT5_P, OUT6_A_N, OUT6_A_P, OUT6_N, OUT6_P, OUT7_A_N, OUT7_A_P, OUT7_N, OUT7_P, OUT8_A_N, OUT8_A_P, OUT8_N, OUT8_P, OUT9_A_N, OUT9_A_P, OUT9_N, OUT9_P, SMA_O4_N, SMA_O4_P, SMA_O5_N, SMA_O5_P, SMA_O6_N, SMA_O6_P, SMA_O7_N, SMA_O7_P, SMA_O8_N, SMA_O8_P, SMA_O9_N, SMA_O9_P
net class OUT_LenMatch2a: OUT4_A_N, OUT4_A_P, OUT5_A_N, OUT5_A_P, OUT6_A_N, OUT6_A_P, OUT8_A_N, OUT8_A_P, OUT9_A_N, OUT9_A_P
net class OUT_LenMatch1a: OUT7_A_N, OUT7_A_P
net class OUT_LenMatch2b: SMA_O4_N, SMA_O4_P, SMA_O5_N, SMA_O5_P, SMA_O6_N, SMA_O6_P, SMA_O8_N, SMA_O8_P, SMA_O9_N, SMA_O9_P
net class OUT_LenMatch1b: SMA_O7_N, SMA_O7_P

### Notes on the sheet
- OUT4 to OUT9 CLOCK OUTPUTS
- OUT4, Supported formats: LVDS, HSDS, and HCSL Source may be VCO2 or VCO3
- OUT5, Supported formats: LVDS, HSDS, and HCSL; Source may be VCO2 or VCO3
- OUT6, Supported formats: LVDS, HSDS, and HCSL Source may be VCO2 or VCO3
- OUT7, Supported formats: LVDS, HSDS, and HCSL; Source may be VCO2 or VCO3
- OUT8, Supported formats: LVDS, HSDS, and HCSL; Source may be VCO2 or VCO3
- OUT9, Supported formats: LVDS, HSDS, and HCSL; Source may be VCO2 or VCO3

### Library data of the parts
C105-C116 = CMP-0006659-2: as C98 on sheet LMK5B33414_Outputs_A
J17-J28 = CMP-0088000-4: as J9-J16 on sheet LMK5B33414_Outputs_A
R89 R91 R93 R95 R97 R98 R100 R102 R104 R106-R108 = CMP-0027007-2: as R6 on sheet LMK5B33414_Outputs_A
R94 R99 R101 R103 R105 R111 R113 R115 R117 R119 = CMP-0026703-1: as R78 on sheet LMK5B33414_Outputs_A
R96 R109 = CMP-0026703-1: RES, 49.9, 1%, 0.1 W, AEC-Q200 Grade 0, 0402; Manufacturer: Panasonic; CompType: Resistor; Value: 49.9; Value_Code: 49R9; Power_W: 100mW; Value2: 0.1W; VDC_V: 50V; TempCo: 100 ppm/C; EIA_Code: E96; SizeArea_mm2: 0.5; SizeX_mm: 1; SizeZ_mm: 0.6; AEC Category: Q200; AEC Qualified: Y; AEC Grade: 0; U/M: EA
R175-R184 R204 R205 = CMP-0026703-1: as R167 on sheet LMK5B33414_Outputs_A

## Sheet LMK5B33414_Outputs_C.SchDoc
size C; Date: Not shown in title block; ApprovedBy: Not shown in title block; CheckedBy: Not shown in title block; Author: Not shown in title block; CompanyName: Not shown in title block; Engineer: Not shown in title block; Organization: Not shown in title block; Address1: Not shown in title block; Address2: Not shown in title block; Address3: Not shown in title block; Address4: Not shown in title block; DocumentNumber: 2; Revision: Use project parameter SCH_Rev; SheetNumber: 2; SheetTotal: 3; PageSetup: Record=PageOptions¦CenterHorizontal=True¦CenterVertical=True¦PrintScale=1.00¦XCorrection=1.00¦YCorrection=1.00¦PrintKind=0¦BorderSize=5000000¦LeftOffset=0¦BottomOffset=0¦Orientation=2¦PaperLength=1000¦PaperWidth=1000¦Scale=100¦PaperSource=15¦PrintQuality=600¦MediaType=1¦DitherType=10¦PaperKind=Letter¦PrintScaleMode=1
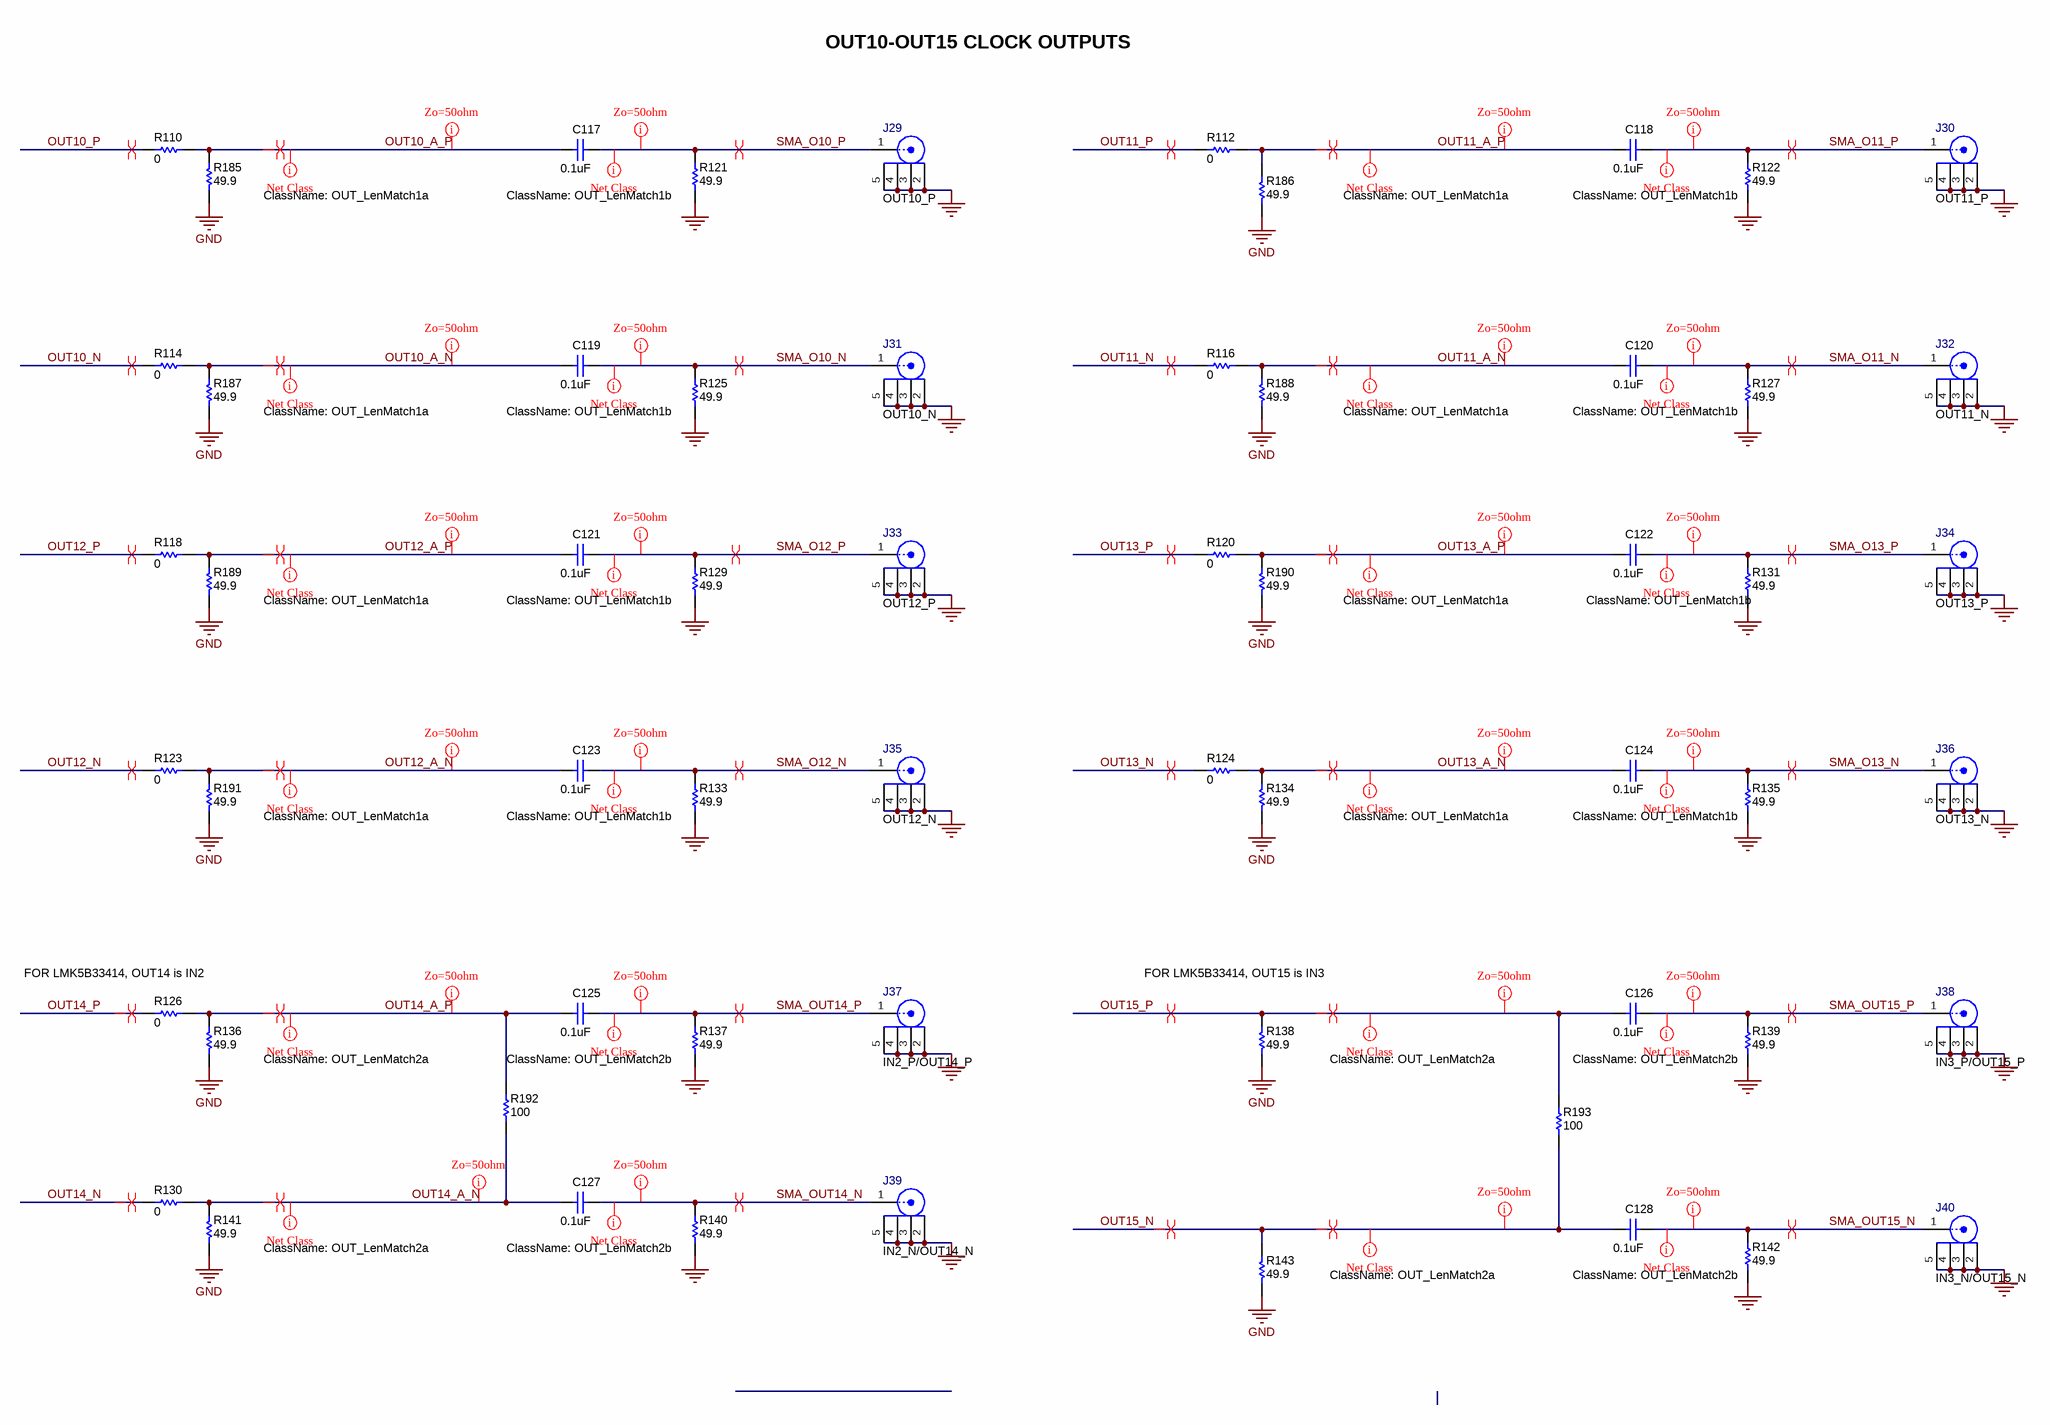
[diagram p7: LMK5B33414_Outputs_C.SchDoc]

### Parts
C117  ValueDisplayed: 0.1uF  [0402L]  (hidden comment: GRM155R71E104KE14D)
C118  ValueDisplayed: 0.1uF  [0402L]  (hidden comment: GRM155R71E104KE14D)
C119  ValueDisplayed: 0.1uF  [0402L]  (hidden comment: GRM155R71E104KE14D)
C120  ValueDisplayed: 0.1uF  [0402L]  (hidden comment: GRM155R71E104KE14D)
C121  ValueDisplayed: 0.1uF  [0402L]  (hidden comment: GRM155R71E104KE14D)
C122  ValueDisplayed: 0.1uF  [0402L]  (hidden comment: GRM155R71E104KE14D)
C123  ValueDisplayed: 0.1uF  [0402L]  (hidden comment: GRM155R71E104KE14D)
C124  ValueDisplayed: 0.1uF  [0402L]  (hidden comment: GRM155R71E104KE14D)
C125  ValueDisplayed: 0.1uF  [0402L]  (hidden comment: GRM155R71E104KE14D)
C126  ValueDisplayed: 0.1uF  [0402L]  (hidden comment: GRM155R71E104KE14D)
C127  ValueDisplayed: 0.1uF  [0402L]  (hidden comment: GRM155R71E104KE14D)
C128  ValueDisplayed: 0.1uF  [0402L]  (hidden comment: GRM155R71E104KE14D)
J29  OUT10_P  [FP-CON-SMA-EDGE-S_CONN_JACK-MFG]
J30  OUT11_P  [FP-CON-SMA-EDGE-S_CONN_JACK-MFG]
J31  OUT10_N  [FP-CON-SMA-EDGE-S_CONN_JACK-MFG]
J32  OUT11_N  [FP-CON-SMA-EDGE-S_CONN_JACK-MFG]
J33  OUT12_P  [FP-CON-SMA-EDGE-S_CONN_JACK-MFG]
J34  OUT13_P  [FP-CON-SMA-EDGE-S_CONN_JACK-MFG]
J35  OUT12_N  [FP-CON-SMA-EDGE-S_CONN_JACK-MFG]
J36  OUT13_N  [FP-CON-SMA-EDGE-S_CONN_JACK-MFG]
J37  IN2_P/OUT14_P  [FP-CON-SMA-EDGE-S_CONN_JACK-MFG]
J38  IN3_P/OUT15_P  [FP-CON-SMA-EDGE-S_CONN_JACK-MFG]
J39  IN2_N/OUT14_N  [FP-CON-SMA-EDGE-S_CONN_JACK-MFG]
J40  IN3_N/OUT15_N  [FP-CON-SMA-EDGE-S_CONN_JACK-MFG]
R110  ValueDisplayed: 0  [0402L]  (hidden comment: RK73Z1ETTP)
R112  ValueDisplayed: 0  [0402L]  (hidden comment: RK73Z1ETTP)
R114  ValueDisplayed: 0  [0402L]  (hidden comment: RK73Z1ETTP)
R116  ValueDisplayed: 0  [0402L]  (hidden comment: RK73Z1ETTP)
R118  ValueDisplayed: 0  [0402L]  (hidden comment: RK73Z1ETTP)
R120  ValueDisplayed: 0  [0402L]  (hidden comment: RK73Z1ETTP)
R121  ValueDisplayed: 49.9  [0402S]  (hidden comment: ERJ-2RKF49R9X)
R122  ValueDisplayed: 49.9  [0402S]  (hidden comment: ERJ-2RKF49R9X)
R123  ValueDisplayed: 0  [0402L]  (hidden comment: RK73Z1ETTP)
R124  ValueDisplayed: 0  [0402L]  (hidden comment: RK73Z1ETTP)
R125  ValueDisplayed: 49.9  [0402S]  (hidden comment: ERJ-2RKF49R9X)
R126  ValueDisplayed: 0  [0402L]  (hidden comment: RK73Z1ETTP)
R127  ValueDisplayed: 49.9  [0402S]  (hidden comment: ERJ-2RKF49R9X)
R129  ValueDisplayed: 49.9  [0402S]  (hidden comment: ERJ-2RKF49R9X)
R130  ValueDisplayed: 0  [0402L]  (hidden comment: RK73Z1ETTP)
R131  ValueDisplayed: 49.9  [0402S]  (hidden comment: ERJ-2RKF49R9X)
R133  ValueDisplayed: 49.9  [0402S]  (hidden comment: ERJ-2RKF49R9X)
R134  ValueDisplayed: 49.9  [0402S]  (hidden comment: ERJ-2RKF49R9X)
R135  ValueDisplayed: 49.9  [0402S]  (hidden comment: ERJ-2RKF49R9X)
R136  ValueDisplayed: 49.9  [0402S]  (hidden comment: ERJ-2RKF49R9X)
R137  ValueDisplayed: 49.9  [0402S]  (hidden comment: ERJ-2RKF49R9X)
R138  ValueDisplayed: 49.9  [0402S]  (hidden comment: ERJ-2RKF49R9X)
R139  ValueDisplayed: 49.9  [0402S]  (hidden comment: ERJ-2RKF49R9X)
R140  ValueDisplayed: 49.9  [0402S]  (hidden comment: ERJ-2RKF49R9X)
R141  ValueDisplayed: 49.9  [0402S]  (hidden comment: ERJ-2RKF49R9X)
R142  ValueDisplayed: 49.9  [0402S]  (hidden comment: ERJ-2RKF49R9X)
R143  ValueDisplayed: 49.9  [0402S]  (hidden comment: ERJ-2RKF49R9X)
R185  ValueDisplayed: 49.9  [0402S]  (hidden comment: ERJ-2RKF49R9X)
R186  ValueDisplayed: 49.9  [0402S]  (hidden comment: ERJ-2RKF49R9X)
R187  ValueDisplayed: 49.9  [0402S]  (hidden comment: ERJ-2RKF49R9X)
R188  ValueDisplayed: 49.9  [0402S]  (hidden comment: ERJ-2RKF49R9X)
R189  ValueDisplayed: 49.9  [0402S]  (hidden comment: ERJ-2RKF49R9X)
R190  ValueDisplayed: 49.9  [0402S]  (hidden comment: ERJ-2RKF49R9X)
R191  ValueDisplayed: 49.9  [0402S]  (hidden comment: ERJ-2RKF49R9X)
R192  ValueDisplayed: 100  [0402L]  (hidden comment: CRCW0402100RFKED)
R193  ValueDisplayed: 100  [0402L]  (hidden comment: CRCW0402100RFKED)

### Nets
GND: J29.2 J29.3 J29.4 J29.5 J30.2 J30.3 J30.4 J30.5 J31.2 J31.3 J31.4 J31.5 J32.2 J32.3 J32.4 J32.5 J33.2 J33.3 J33.4 J33.5 J34.2 J34.3 J34.4 J34.5 J35.2 J35.3 J35.4 J35.5 J36.2 J36.3 J36.4 J36.5 J37.2 J37.3 J37.4 J37.5 J38.2 J38.3 J38.4 J38.5 J39.2 J39.3 J39.4 J39.5 J40.2 J40.3 J40.4 J40.5 R121.1 R122.1 R125.1 R127.1 R129.1 R131.1 R133.1 R134.2 R135.1 R136.2 R137.1 R138.2 R139.1 R140.1 R141.2 R142.1 R143.2 R185.2 R186.2 R187.2 R188.2 R189.2 R190.2 R191.2
OUT10_A_N: C119.2 R114.2 R187.1
OUT10_A_P: C117.2 R110.2 R185.1
OUT10_N: R114.1
OUT10_P: R110.1
OUT11_A_N: C120.2 R116.2 R188.1
OUT11_A_P: C118.2 R112.2 R186.1
OUT11_N: R116.1
OUT11_P: R112.1
OUT12_A_N: C123.2 R123.2 R191.1
OUT12_A_P: C121.2 R118.2 R189.1
OUT12_N: R123.1
OUT12_P: R118.1
OUT13_A_N: C124.2 R124.2 R134.1
OUT13_A_P: C122.2 R120.2 R190.1
OUT13_N: R124.1
OUT13_P: R120.1
OUT14_A_N: C127.2 R130.2 R141.1 R192.1
OUT14_A_P: C125.2 R126.2 R136.1 R192.2
OUT14_N: R130.1
OUT14_P: R126.1
OUT15_N: C128.2 R143.1 R193.1
OUT15_P: C126.2 R138.1 R193.2
SMA_O10_N: C119.1 J31.1 R125.2
SMA_O10_P: C117.1 J29.1 R121.2
SMA_O11_N: C120.1 J32.1 R127.2
SMA_O11_P: C118.1 J30.1 R122.2
SMA_O12_N: C123.1 J35.1 R133.2
SMA_O12_P: C121.1 J33.1 R129.2
SMA_O13_N: C124.1 J36.1 R135.2
SMA_O13_P: C122.1 J34.1 R131.2
SMA_OUT14_N: C127.1 J39.1 R140.2
SMA_OUT14_P: C125.1 J37.1 R137.2
SMA_OUT15_N: C128.1 J40.1 R142.2
SMA_OUT15_P: C126.1 J38.1 R139.2

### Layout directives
rule Impedance Constraint [Min = 45.00    Max = 55.00    ]: OUT10_A_N, OUT10_A_P, OUT11_A_N, OUT11_A_P, OUT12_A_N, OUT12_A_P, OUT13_A_N, OUT13_A_P, OUT14_A_N, OUT14_A_P, OUT15_N, OUT15_P, SMA_O10_N, SMA_O10_P, SMA_O11_N, SMA_O11_P, SMA_O12_N, SMA_O12_P, SMA_O13_N, SMA_O13_P, SMA_OUT14_N, SMA_OUT14_P, SMA_OUT15_N, SMA_OUT15_P
differential pair: OUT10_A_N, OUT10_A_P, OUT10_N, OUT10_P, OUT11_A_N, OUT11_A_P, OUT11_N, OUT11_P, OUT12_A_N, OUT12_A_P, OUT12_N, OUT12_P, OUT13_A_N, OUT13_A_P, OUT13_N, OUT13_P, OUT14_A_N, OUT14_A_P, OUT14_N, OUT14_P, OUT15_N, OUT15_P, SMA_O10_N, SMA_O10_P, SMA_O11_N, SMA_O11_P, SMA_O12_N, SMA_O12_P, SMA_O13_N, SMA_O13_P, SMA_OUT14_N, SMA_OUT14_P, SMA_OUT15_N, SMA_OUT15_P
net class OUT_LenMatch1a: OUT10_A_N, OUT10_A_P, OUT11_A_N, OUT11_A_P, OUT12_A_N, OUT12_A_P, OUT13_A_N, OUT13_A_P
net class OUT_LenMatch2a: OUT14_A_N, OUT14_A_P, OUT15_N, OUT15_P
net class OUT_LenMatch2b: SMA_OUT14_N, SMA_OUT14_P, SMA_OUT15_N, SMA_OUT15_P
net class OUT_LenMatch1b: SMA_O10_N, SMA_O10_P, SMA_O11_N, SMA_O11_P, SMA_O12_N, SMA_O12_P, SMA_O13_N, SMA_O13_P

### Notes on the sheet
- OUT10-OUT15 CLOCK OUTPUTS
- FOR LMK5B33414, OUT14 is IN2
- (near R138) FOR LMK5B33414, OUT15 is IN3

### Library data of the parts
C117-C128 = CMP-0006659-2: as C98 on sheet LMK5B33414_Outputs_A
J29-J40 = CMP-0088000-4: as J9-J16 on sheet LMK5B33414_Outputs_A
R110 R112 R114 R116 R118 R120 R123 R124 R126 R130 = CMP-0027007-2: as R6 on sheet LMK5B33414_Outputs_A
R121 R122 R125 R127 R129 R131 R133 R135 R137 R139 R140 R142 = CMP-0026703-1: as R78 on sheet LMK5B33414_Outputs_A
R134 R136 R138 R141 R143 R185-R191 = CMP-0026703-1: as R167 on sheet LMK5B33414_Outputs_A
R192 R193 = CMP-0025951-3: RES, 100, 1%, 0.063 W, AEC-Q200 Grade 0, 0402; Manufacturer: Vishay-Dale; CompType: Resistor; Value: 100; Value_Code: 100R; Power_W: 63mW; Value2: 0.063W; VDC_V: 50V; TempCo: 100 ppm/C; EIA_Code: E96; AEC Category: Q200; AEC Qualified: Y; AEC Grade: 0; SizeArea_mm2: 0.5; SizeX_mm: 1; SizeZ_mm: 0.6

## Sheet LMK5B33414_XO.SchDoc
size C; Date: Not shown in title block; ApprovedBy: Not shown in title block; CheckedBy: Not shown in title block; Author: Not shown in title block; CompanyName: Not shown in title block; Engineer: Not shown in title block; Organization: Not shown in title block; Address1: Not shown in title block; Address2: Not shown in title block; Address3: Not shown in title block; Address4: Not shown in title block; DocumentNumber: 1; Revision: Use project parameter SCH_Rev; SheetNumber: 2; SheetTotal: 3; PageSetup: Record=PageOptions¦CenterHorizontal=True¦CenterVertical=True¦PrintScale=1.00¦XCorrection=1.00¦YCorrection=1.00¦PrintKind=0¦BorderSize=5000000¦LeftOffset=0¦BottomOffset=0¦Orientation=2¦PaperLength=1000¦PaperWidth=1000¦Scale=100¦PaperSource=15¦PrintQuality=600¦MediaType=1¦DitherType=10¦PaperKind=Letter¦PrintScaleMode=1
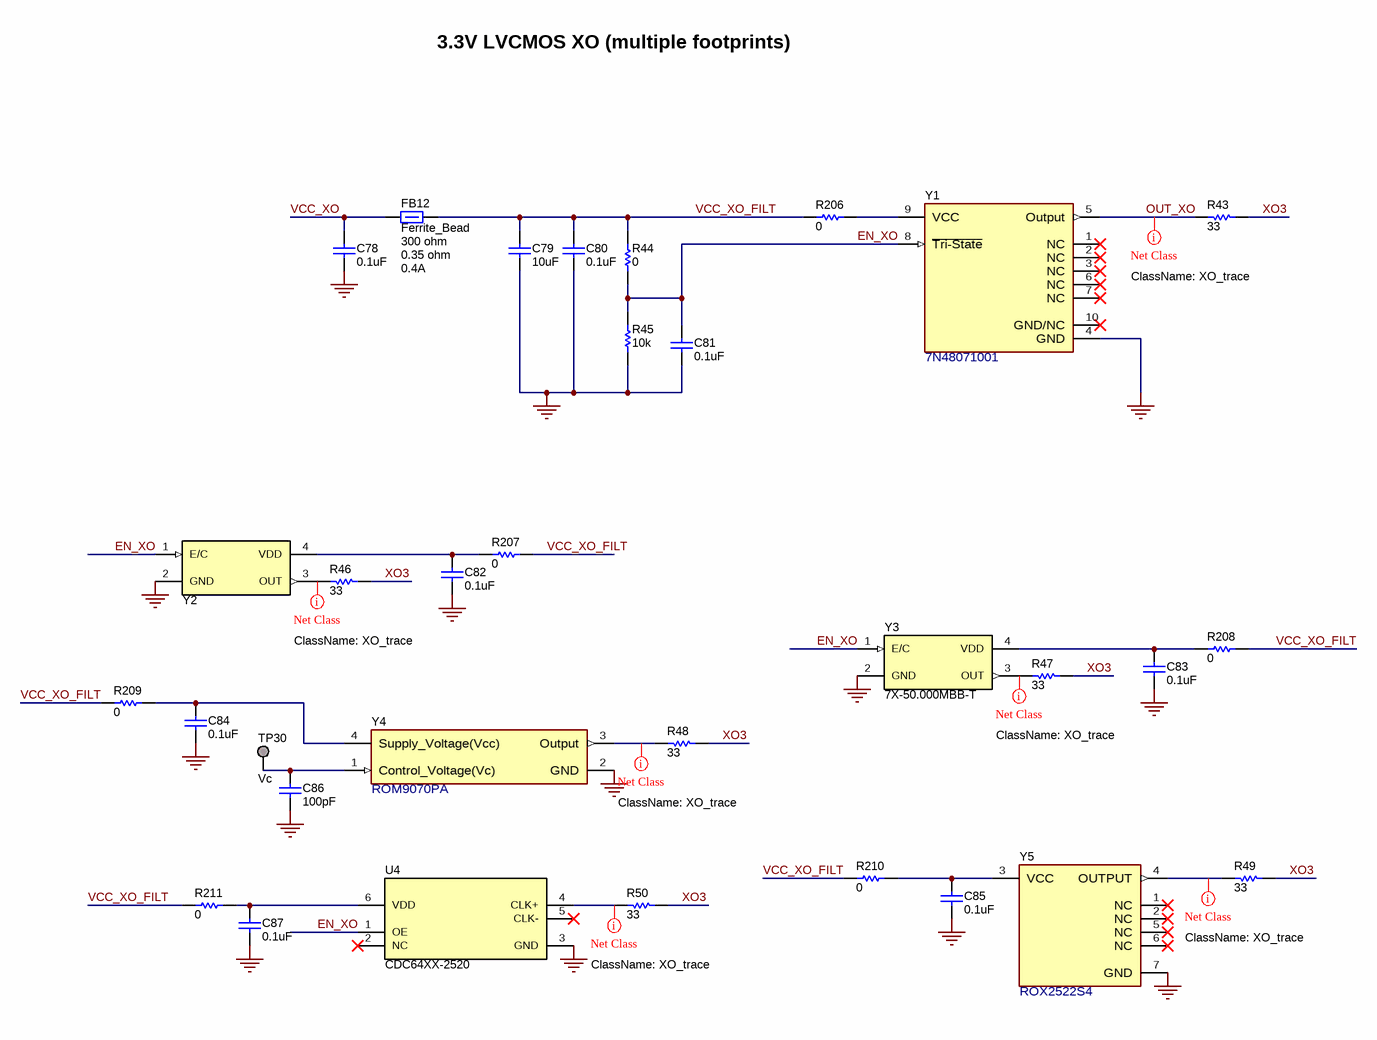
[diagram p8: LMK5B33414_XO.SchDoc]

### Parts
C78  ValueDisplayed: 0.1uF  [0603]  (hidden comment: Capacitor)
C79  ValueDisplayed: 10uF  [0603]  (hidden comment: Capacitor)
C80  ValueDisplayed: 0.1uF  [0603]  (hidden comment: Capacitor)
C81  ValueDisplayed: 0.1uF  [0603]  (hidden comment: Capacitor)
C82  ValueDisplayed: 0.1uF  [0603]  (hidden comment: Capacitor)
C83  ValueDisplayed: 0.1uF  [0603]  (hidden comment: Capacitor)
C84  ValueDisplayed: 0.1uF  [0603]  (hidden comment: Capacitor)
C85  ValueDisplayed: 0.1uF  [0603]  (hidden comment: Capacitor)
C86  ValueDisplayed: 100pF  [0603]  (hidden comment: Capacitor)
C87  ValueDisplayed: 0.1uF  [0603]  (hidden comment: Capacitor)
FB12  Ferrite_Bead  value 300 ohm  Value1: 0.35 ohm  Value2: 0.4A  [LI0603D]
R43  ValueDisplayed: 33  [0402]  (hidden comment: CRCW040233R0JNED)
R44  ValueDisplayed: 0  [0603]  (hidden comment: ERJ-3GEY0R00V)
R45  ValueDisplayed: 10k  [0603]  (hidden comment: Resistor)
R46  ValueDisplayed: 33  [0402S]  (hidden comment: CRCW040233R0JNED)
R47  ValueDisplayed: 33  [0402S]  (hidden comment: CRCW040233R0JNED)
R48  ValueDisplayed: 33  [0402S]  (hidden comment: CRCW040233R0JNED)
R49  ValueDisplayed: 33  [0402S]  (hidden comment: CRCW040233R0JNED)
R50  ValueDisplayed: 33  [0402S]  (hidden comment: CRCW040233R0JNED)
R206  ValueDisplayed: 0  [0603]  (hidden comment: RC0603JR-070RL)
R207  ValueDisplayed: 0  [0603]  (hidden comment: RC0603JR-070RL)
R208  ValueDisplayed: 0  [0603]  (hidden comment: RC0603JR-070RL)
R209  ValueDisplayed: 0  [0603]  (hidden comment: RC0603JR-070RL)
R210  ValueDisplayed: 0  [0603]  (hidden comment: RC0603JR-070RL)
R211  ValueDisplayed: 0  [0603]  (hidden comment: RC0603JR-070RL)
TP30  Vc  [Keystone_5019]
U4  CDC64XX-2520  [DLF0006A]
Y1  7N48071001  [FP-7N48071001_SMT10_7MM0_5MM0-MFG]
Y2  8W48072003  [TXC_8W]  (value not drawn)
Y3  7X-50.000MBB-T  [OSC_TXC-7X]
Y4  ROM9070PA  [FP-ROM9070PA_SMD4-MFG]
Y5  ROX2522S4  [FP-ROX2522S4_SMD_ OCXO7_25MM4_22MM0-MFG]

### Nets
GND: C78.2 C79.1 C80.2 C81.2 C82.2 C83.2 C84.2 C85.2 C86.2 C87.2 R45.2 U4.3(GND) Y1.4(GND) Y2.2(GND) Y3.2(GND) Y4.2(GND) Y5.7(GND)
VCC_XO: C78.1 FB12.2
EN_XO: C81.1 R44.2 R45.1 U4.1(OE) Y1.8(~{Tri-State}) Y2.1(E/C) Y3.1(E/C)
OUT_XO: R43.2 Y1.5(Output)
VCC_XO_FILT: C79.2 C80.1 FB12.1 R44.1 R206.1 R207.2 R208.2 R209.1 R210.1 R211.1
XO3: R43.1 R46.1 R47.1 R48.1 R49.1 R50.1
NetC82_1: C82.1 R207.1 Y2.4(VDD)
NetC83_1: C83.1 R208.1 Y3.4(VDD)
NetC84_1: C84.1 R209.2 Y4.4(Supply_Voltage(Vcc))
NetC85_1: C85.1 R210.2 Y5.3(VCC)
NetC86_1: C86.1 TP30.1 Y4.1(Control_Voltage(Vc))
NetC87_1: C87.1 R211.2 U4.6(VDD)
NetR46_2: R46.2 Y2.3(OUT)
NetR47_2: R47.2 Y3.3(OUT)
NetR48_2: R48.2 Y4.3(Output)
NetR49_2: R49.2 Y5.4(OUTPUT)
NetR50_2: R50.2 U4.4(CLK+)
NetR206_2: R206.2 Y1.9(VCC)

Not connected (* = marked no-connect by the designer): U4 2(NC)* 5(CLK-)*; Y1 1(NC)* 2(NC)* 3(NC)* 6(NC)* 7(NC)* 10(GND/NC)*; Y5 1(NC)* 2(NC)* 5(NC)* 6(NC)*

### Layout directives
net class XO_trace: NetR46_2, NetR47_2, NetR48_2, NetR49_2, NetR50_2, OUT_XO

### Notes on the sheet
- 3.3V LVCMOS XO (multiple footprints)

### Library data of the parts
C78 C80-C85 C87 = CMP-0006856-6: CAP, CERM, 0.1 uF, 25 V, +/- 5%, X7R, 0603; Manufacturer: Kemet; PartNumber: C0603C104J3RACTU; Polarized: N; TaMax_C: 125°C; TaMin_C: -55°C; VDC_V: 25V; Cap_F: 100nF; Value: 0.1uF; Value1: Unknown; U/M: EA; AEC Category: Q200; SizeArea_mm2: 1.28; SizeAreaWB_mm2: 4.68; SizeX_mm: 1.6; SizeY_mm: 0.8; SizeZ_mm: 1
C79 = CMP-0007003-5: CAP, CERM, 10 uF, 10 V, +/- 20%, X5R, 0603; Manufacturer: TDK; PartNumber: C1608X5R1A106M080AC; ESR_ohm: 7.8m; IRMS_A: 1.85A; Polarized: N; TaMax_C: 85°C; TaMin_C: -55°C; VDC_V: 10V; Cap_F: 10µF; Value: 10uF; Value1: 0.0078 ohm; U/M: EA; SizeArea_mm2: 1.28; SizeAreaWB_mm2: 4.68; SizeX_mm: 1.6; SizeY_mm: 0.8; SizeZ_mm: 1; AEC Category: Q200
C86 = CMP-0006763-4: as C88 on sheet LMK5B33414_Logic
FB12 = CMP-0003403-1: Ferrite Bead, 300 ohm @ 100 MHz, 0.4 A, 1.6x0.8x0.95mm; PartNumber: LI0603D301R-10; Manufacturer: Laird-Signal Integrity Products; Imax_A: 4dA; DCR_ohm: 3.5d; ZTyp@100MHz_Ohm: 300; SizeArea_mm2: 1.28; SizeAreaWB_mm2: 4.68; SizeX_mm: 1.6; SizeY_mm: 0.8; SizeZ_mm: 0.95
R43 R46-R50 = CMP-0026908-3: RES, 33, 5%, 0.063 W, AEC-Q200 Grade 0, 0402; Manufacturer: Vishay-Dale; VDC_V: 50V; Power_W: 63mW; Value: 33; Value_Code: 33R0; Value2: 0.063W; EIA_Code: E24; TempCo: 200 ppm/C; AEC Category: Q200; AEC Qualified: Y; AEC Grade: 0; SizeArea_mm2: 0.5; SizeX_mm: 1; SizeZ_mm: 0.6
R44 = CMP-0025874-4: RES, 0, 5%, 0.1 W, AEC-Q200 Grade 0, 0603; Manufacturer: Panasonic; CompType: Resistor; VDC_V: 50V; Power_W: 100mW; Value: 0; Value_Code: 0000; Value2: 0.1W; EIA_Code: E24; TempCo: 600 ppm/C; AEC Category: Q200; AEC Qualified: Y; SizeArea_mm2: 1.28; SizeX_mm: 1.6; SizeY_mm: 0.8; SizeZ_mm: 1; SizeAreaWB_mm2: 4.68
R45 = CMP-0025701-4: RES, 10 k, 5%, 0.1 W, AEC-Q200 Grade 0, 0603; Manufacturer: Vishay-Dale; PartNumber: CRCW060310K0JNEA; VDC_V: 75V; Power_W: 100mW; Value: 10k; Value_Code: 10k0; Value2: 0.1W; EIA_Code: E24; TempCo: 200 ppm/C; AEC Category: Q200; AEC Qualified: Y; AEC Grade: 0; SizeArea_mm2: 1.28; SizeX_mm: 1.6; SizeY_mm: 0.8; SizeZ_mm: 1
R206-R211 = CMP-0025885-5: RES, 0, 5%, 0.1 W, 0603; Manufacturer: Yageo; Power_W: 100mW; TempCo: 200 ppm/C; Value_Code: 0000; Value: 0; EIA_Code: E24; SizeX_mm: 1.6; SizeY_mm: 0.8; SizeZ_mm: 1; Value2: 0.1W; SizeArea_mm2: 1.28; AEC Qualified: N; AEC Category: Q200; VDC_V: 75V; SizeAreaWB_mm2: 4.68
TP30 = CMP-0055162-1: as TP31 on sheet LMK5B33414_Logic
U4 = CMP-0078850-3: CDC64XX-2520, DLF0006A (VSON-6); Alternate Manufacturer: Texas Instruments; SizeZ_mm: 1; AEC Qualified: N; SizeArea_mm2: 5; SizeY_mm: 2.5; AEC Category: Q200; SizeAreaWB_mm2: 10.5; SizeX_mm: 2; CompType: IC
Y1 = CMP-0093851-1: SMD TCXO 7.0 * 5.0 48.000000MHz; Manufacturer: TXC; Frequency Stability: 0.25ppm; Frequency_Fixed: 48MHz; SizeZ_mm: 1.7mm; AEC Qualified: No; Load Capacitance: 15pF; Min Supply Voltage: 2.97V; Max Supply Voltage: 3.63V; Max Supply Current: 10mA
Y2 = CMP-0074743-2: Crystal, 48 MHz, 15 pF, SMD; Manufacturer: TXC Corporation; TaMin_C: -40°C; TaMax_C: 85°C; Frequency Stability: ±50ppm; Frequency_Fixed: 48MHz; SizeAreaWB_mm2: 10.5; SizeArea_mm2: 5.0; SizeX_mm: 2.0; SizeY_mm: 2.5; SizeZ_mm: 0.9
Y3 = CMP-0006115-3: Crystal, Sealed Locked 50 MHz, 15pF, SMD; Manufacturer: TXC Corporation; TaMin_C: -40°C; Frequency Stability: +/-50ppm; Frequency_Fixed: 50MHz; TaMax_C: 85°C; CompType: Oscillator
Y4 = CMP-0088752-1: MERCURY+ 38.88MHz OCXO CMOS Oscillator 2.7 ~ 5V 4-SMD; Manufacturer: Rakon; AEC Qualified: No; SizeZ_mm: 4.1mm; Min Supply Voltage: 2.7V; Frequency Stability: 0.01ppm
Y5 = CMP-0088753-1: STANDARD OCXO 10MHz Frequency; Manufacturer: Rakon; Max Supply Voltage: 3.465V; SizeZ_mm: 15.4mm; Min Supply Voltage: 3.135V; AEC Qualified: No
